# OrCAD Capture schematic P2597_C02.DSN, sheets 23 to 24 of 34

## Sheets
23 11_SDcard Slot: size Custom
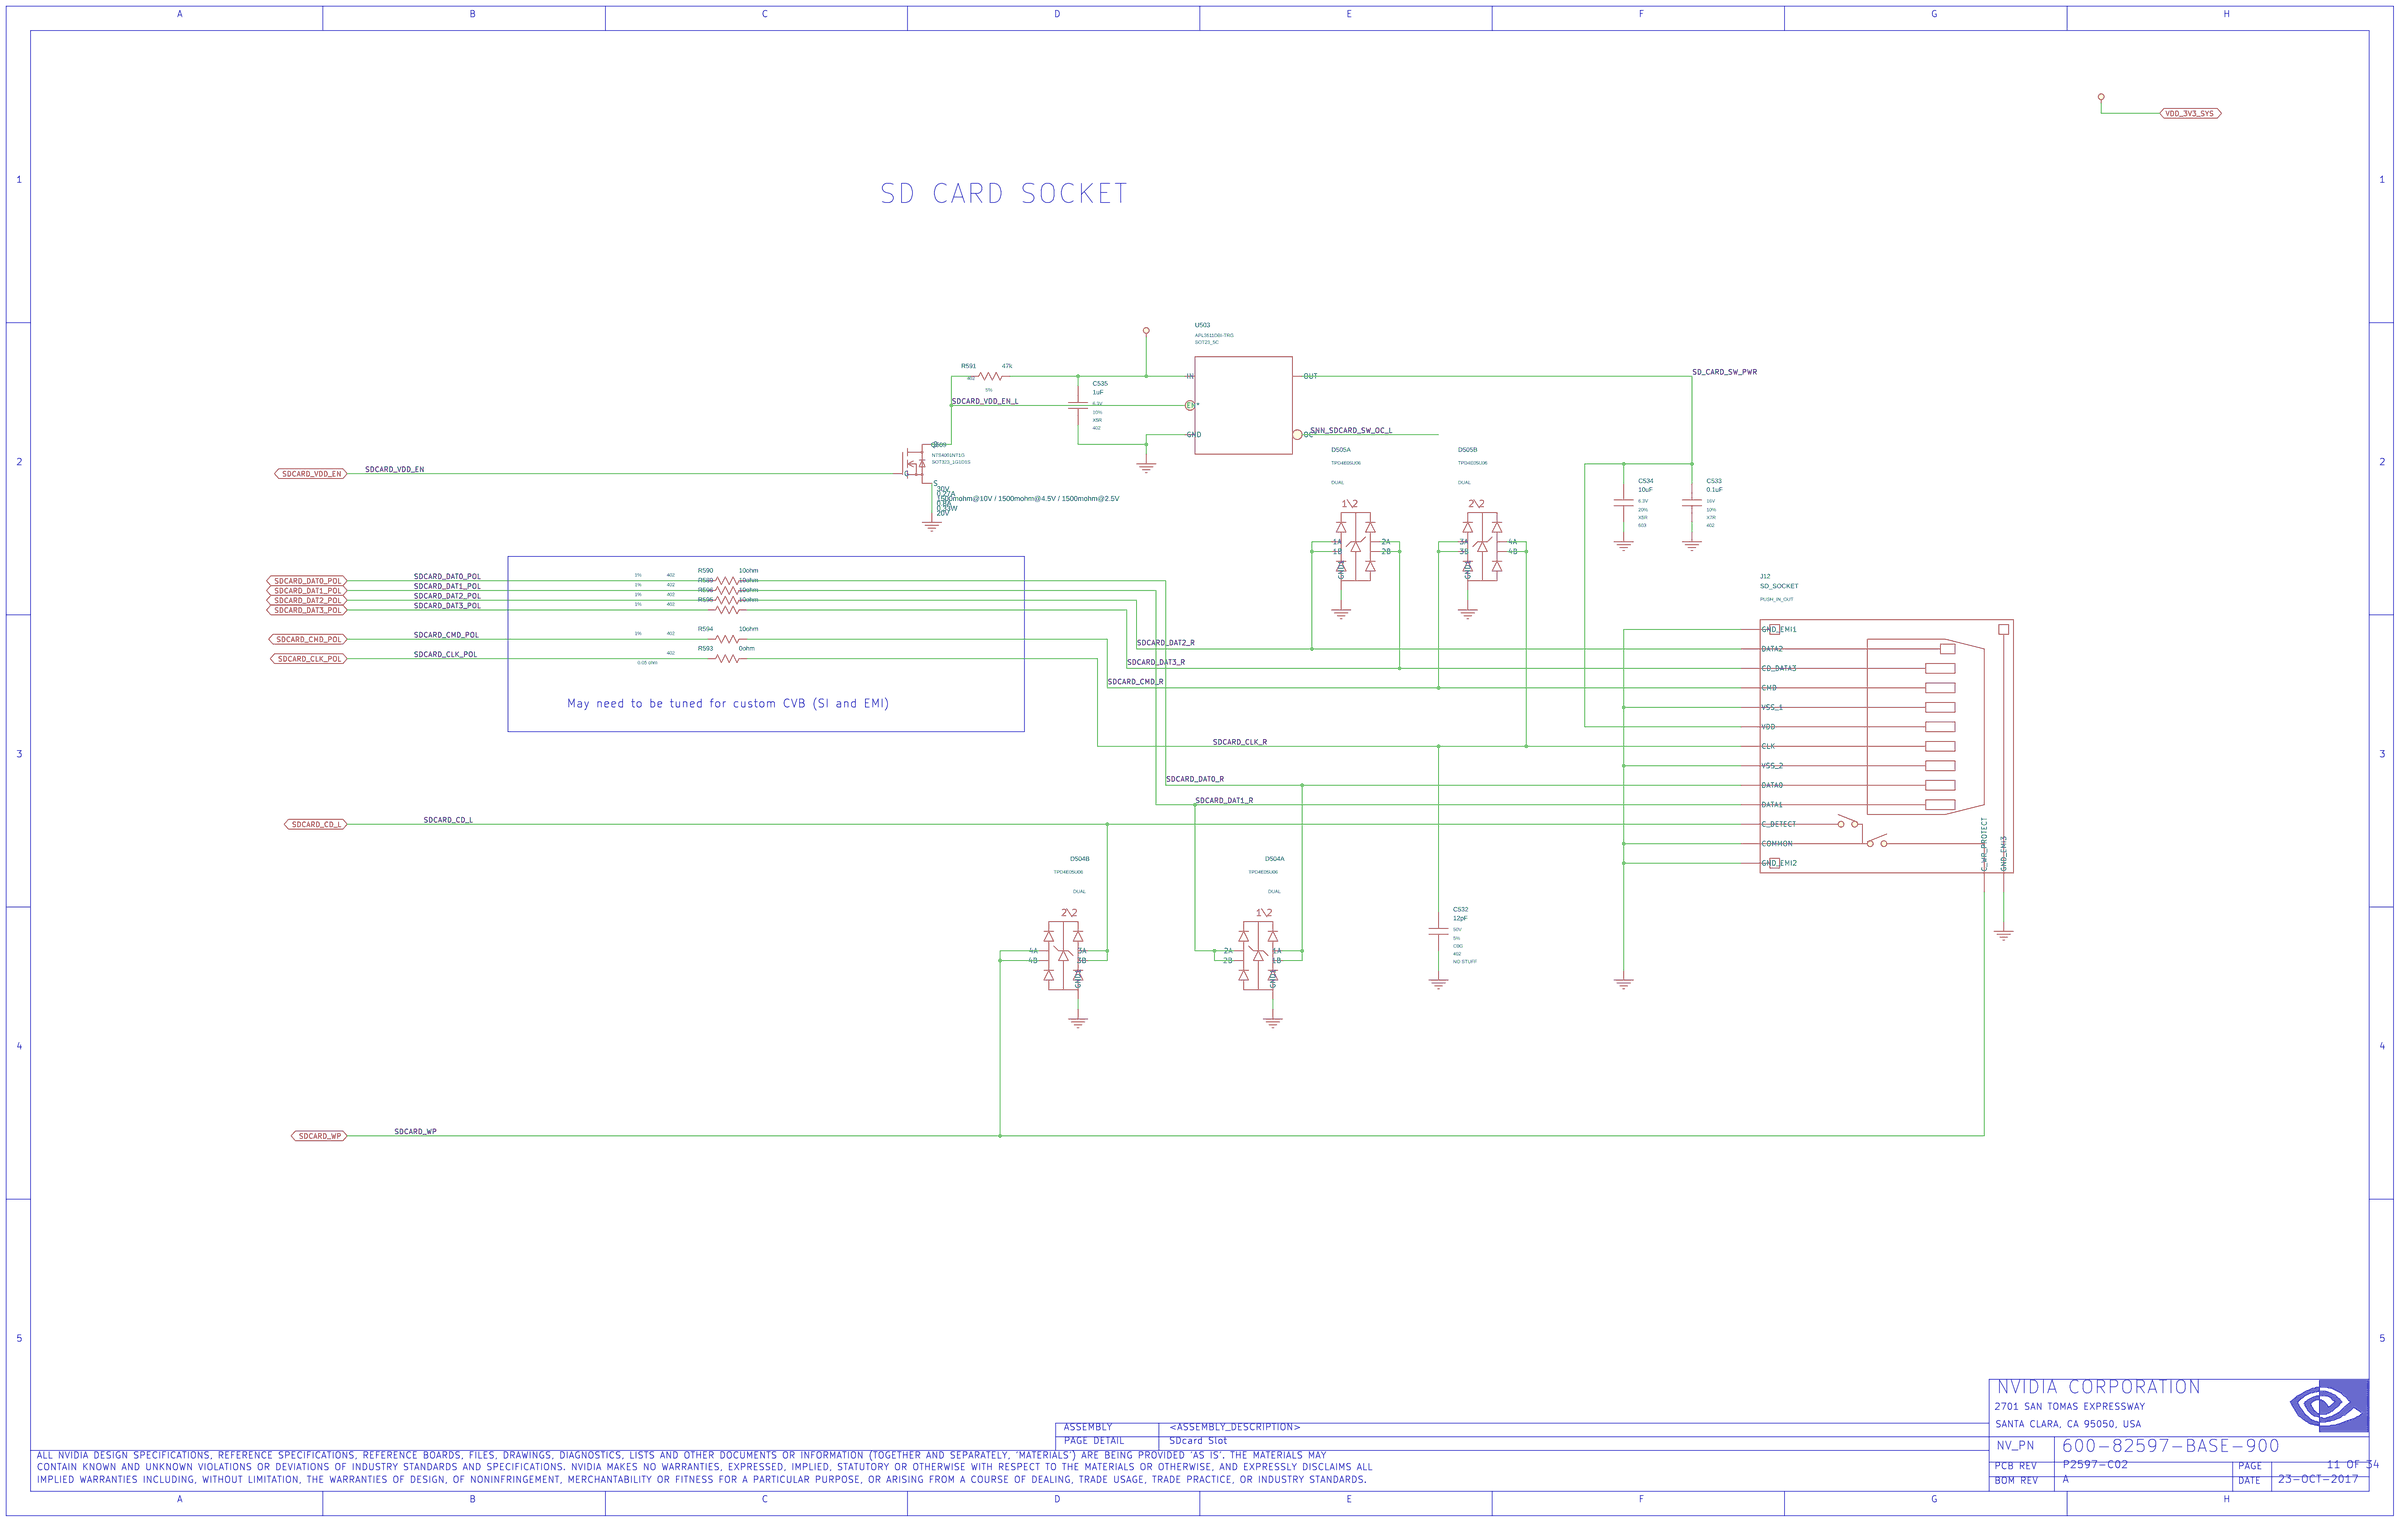
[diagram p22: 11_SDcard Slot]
24 10_M.2 KEY E: size Custom
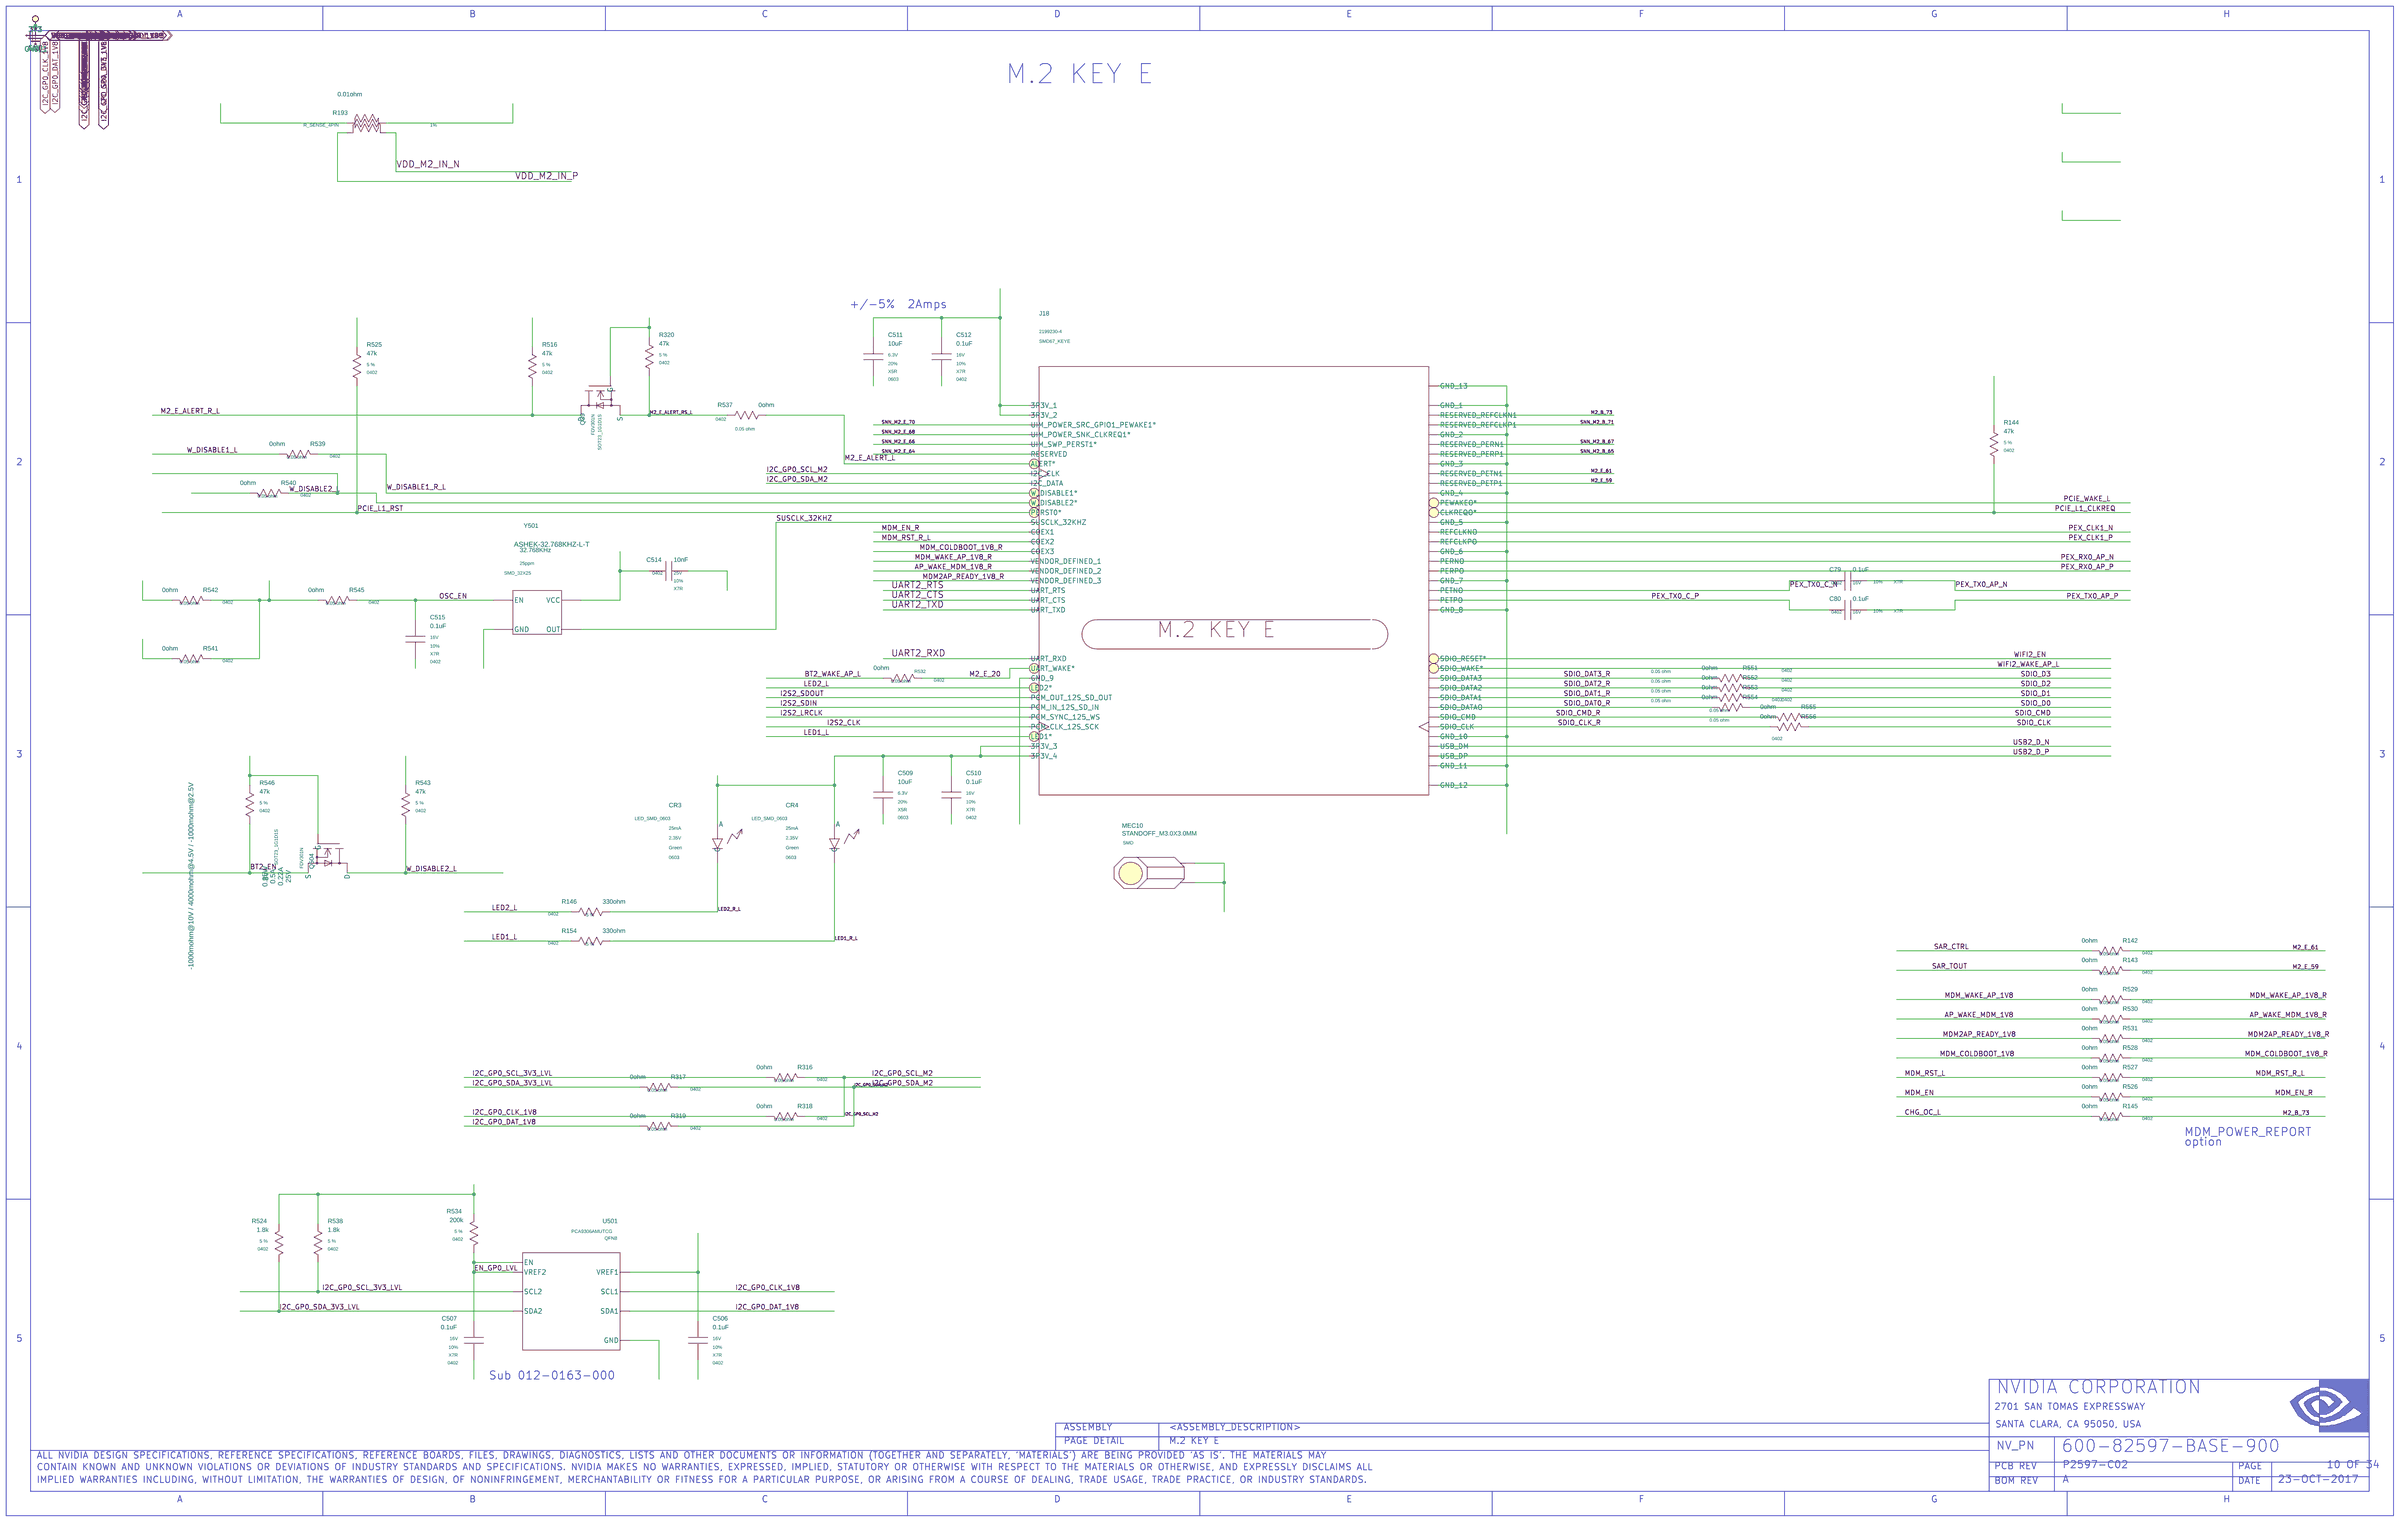
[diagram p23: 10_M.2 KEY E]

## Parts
sheet 10_M.2 KEY E
C79  0.1uF  [0402]
C80  0.1uF  [0402]
C506  0.1uF  [0402]
C507  0.1uF  [0402]
C509  10uF  [0603]
C510  0.1uF  [0402]
C511  10uF  [0603]
C512  0.1uF  [0402]
C514  10nF  [0402]
C515  0.1uF  [0402]
CR3  LED  [LED_SMD_0603_ST]
CR4  LED  [LED_SMD_0603_ST]
J18  CON_M2_PCI_EXP  [CON_MINIPEX_067_SMT_RA_M2_KEYE]
MEC10  MEC_STANDOFF2  [MEC_HOLE_PEM_NTH_430P]
Q39  Q_FET_N_ENH  [SOT23]
Q504  Q_FET_N_ENH  [SOT23]
R142  0ohm  [0402]
R143  0ohm  [0402]
R144  47k  [0402]
R145  0ohm  [0402]
R146  330ohm  [0402]
R154  330ohm  [0402]
R193  0.01ohm  [RES_04_SMD_015X032]
R316  0ohm  [0402]
R317  0ohm  [0402]
R318  0ohm  [0402]
R319  0ohm  [0402]
R320  47k  [0402]
R516  47k  [0402]
R524  1.8k  [0402]
R525  47k  [0402]
R526  0ohm  [0402]
R527  0ohm  [0402]
R528  0ohm  [0402]
R529  0ohm  [0402]
R530  0ohm  [0402]
R531  0ohm  [0402]
R532  0ohm  [0402]
R534  200k  [0402]
R537  0ohm  [0402]
R538  1.8k  [0402]
R539  0ohm  [0402]
R540  0ohm  [0402]
R541  0ohm  [0402]
R542  0ohm  [0402]
R543  47k  [0402]
R545  0ohm  [0402]
R546  47k  [0402]
R551  0ohm  [0402]
R552  0ohm  [0402]
R553  0ohm  [0402]
R554  0ohm  [0402]
R555  0ohm  [0402]
R556  0ohm  [0402]
U501  U_I2C_PCA9306  [QFN008Q_P050_0016X0016]
Y501  32.768KHz  [XTAL_SMD_4_032X025]
sheet 11_SDcard Slot
C532  12pF  [402]
C533  0.1uF  [402]
C534  10uF  [603]
C535  1uF  [402]
D504  D_ESD_DIFFPAIR#1  [TSLP10_P050_025X010]  (sections A,B)
D505  D_ESD_DIFFPAIR#1  [TSLP10_P050_025X010]  (sections A,B)
J12  CON_SD_SOCKET  [CON_SD_012_SMD_RA]
Q509  Q_FET_N_ENH  [SOT323]
R589  10ohm  [402]
R590  10ohm  [402]
R591  47k  [402]
R593  0ohm  [402]
R594  10ohm  [402]
R595  10ohm  [402]
R596  10ohm  [402]
U503  U_POWER_SW  [SOT23_5]

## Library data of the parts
C79 = C#1: ASSEMBLY: PEX_MINI; CDS_LIB: discrete; CDS_PART_NAME: C_0402-0.1UF,X7R,10%,16V,036-0014-000; CDS_PHYS_PART_NAME: C_0402-0.1UF,X7R,10%,16V,036-0014-000-0.1UF,036-0014-000; CDS_SEC: 1; CHIPS_PART_NAME: C; DEVICE_TYPENAME: C_0402-01UFX7R1016V036-0014-000-01UF036-0014-000; DRAWING: @P2597_C02_LIB.P2597_C02(SCH_1):PAGE10; MAT: X7R; MAX_VOLTAGE: 16V; NV_PN: 036-0014-000; PATH: I307; PHYS_PAGE: 10; ROT: 0; SEC: 1; SIGNAL_MODEL: nv_cap; TOL: 10%; VER: 2; XY: (-3000,6150)
C80 = C#1: ASSEMBLY: PEX_MINI; CDS_LIB: discrete; CDS_PART_NAME: C_0402-0.1UF,X7R,10%,16V,036-0014-000; CDS_PHYS_PART_NAME: C_0402-0.1UF,X7R,10%,16V,036-0014-000-0.1UF,036-0014-000; CDS_SEC: 1; CHIPS_PART_NAME: C; DEVICE_TYPENAME: C_0402-01UFX7R1016V036-0014-000-01UF036-0014-000; DRAWING: @P2597_C02_LIB.P2597_C02(SCH_1):PAGE10; MAT: X7R; MAX_VOLTAGE: 16V; NV_PN: 036-0014-000; PATH: I308; PHYS_PAGE: 10; ROT: 0; SEC: 1; SIGNAL_MODEL: nv_cap; TOL: 10%; VER: 2; XY: (-3000,6000)
C506 = C: ASSEMBLY: GEN1_CONV; CDS_LIB: discrete; CDS_PART_NAME: C_0402-0.1UF,X7R,10%,16V,036-0014-000; CDS_PHYS_PART_NAME: C_0402-0.1UF,X7R,10%,16V,036-0014-000-0.1UF,036-0014-000; CDS_SEC: 1; DEVICE_TYPENAME: C_0402-01UFX7R1016V036-0014-000-01UF036-0014-000; DRAWING: @P2597_C02_LIB.P2597_C02(SCH_1):PAGE10; MAT: X7R; MAX_VOLTAGE: 16V; NV_PN: 036-0014-000; PATH: I273; PHYS_PAGE: 10; ROT: 0; SEC: 1; SIGNAL_MODEL: nv_cap; TOL: 10%; VER: 1; XY: (-8900,2250)
C507 = C: ASSEMBLY: GEN1_CONV; CDS_LIB: discrete; CDS_PART_NAME: C_0402-0.1UF,X7R,10%,16V,036-0014-000; CDS_PHYS_PART_NAME: C_0402-0.1UF,X7R,10%,16V,036-0014-000-0.1UF,036-0014-000; CDS_SEC: 1; DEVICE_TYPENAME: C_0402-01UFX7R1016V036-0014-000-01UF036-0014-000; DRAWING: @P2597_C02_LIB.P2597_C02(SCH_1):PAGE10; MAT: X7R; MAX_VOLTAGE: 16V; NV_PN: 036-0014-000; PATH: I267; PHYS_PAGE: 10; ROT: 2; SEC: 1; SIGNAL_MODEL: nv_cap; TOL: 10%; VER: 1; XY: (-10050,2250)
C509 = C: ASSEMBLY: PEX_MINI; CDS_LIB: discrete; CDS_PART_NAME: C_0603-10UF,X5R,20%,6.3V,039-0135-000; CDS_PHYS_PART_NAME: C_0603-10UF,X5R,20%,6.3V,039-0135-000-039-0135-000,10UF; CDS_SEC: 1; DEVICE_TYPENAME: C_0603-10UFX5R2063V039-0135-000-039-0135-00010UF; DRAWING: @P2597_C02_LIB.P2597_C02(SCH_1):PAGE10; MAT: X5R; MAX_VOLTAGE: 6.3V; NV_PN: 039-0135-000; PATH: I169; PHYS_PAGE: 10; ROT: 0; SEC: 1; SIGNAL_MODEL: DEFAULT_CAPACITOR_1e+07pF_2_1; TOL: 20%; VER: 1; XY: (-7950,5050)
C510 = C: ASSEMBLY: PEX_MINI; CDS_LIB: discrete; CDS_PART_NAME: C_0402-0.1UF,X7R,10%,16V,036-0014-000; CDS_PHYS_PART_NAME: C_0402-0.1UF,X7R,10%,16V,036-0014-000-0.1UF,036-0014-000; CDS_SEC: 1; DEVICE_TYPENAME: C_0402-01UFX7R1016V036-0014-000-01UF036-0014-000; DRAWING: @P2597_C02_LIB.P2597_C02(SCH_1):PAGE10; MAT: X7R; MAX_VOLTAGE: 16V; NV_PN: 036-0014-000; PATH: I171; PHYS_PAGE: 10; ROT: 0; SEC: 1; SIGNAL_MODEL: DEFAULT_CAPACITOR_100000pF_2_1; TOL: 10%; VER: 1; XY: (-7600,5050)
C511 = C: ASSEMBLY: PEX_MINI; CDS_LIB: discrete; CDS_PART_NAME: C_0603-10UF,X5R,20%,6.3V,039-0135-000; CDS_PHYS_PART_NAME: C_0603-10UF,X5R,20%,6.3V,039-0135-000-039-0135-000,10UF; CDS_SEC: 1; DEVICE_TYPENAME: C_0603-10UFX5R2063V039-0135-000-039-0135-00010UF; DRAWING: @P2597_C02_LIB.P2597_C02(SCH_1):PAGE10; MAT: X5R; MAX_VOLTAGE: 6.3V; NV_PN: 039-0135-000; PATH: I165; PHYS_PAGE: 10; ROT: 0; SEC: 1; SIGNAL_MODEL: DEFAULT_CAPACITOR_1e+07pF_2_1; TOL: 20%; VER: 1; XY: (-8000,7300)
C512 = C: ASSEMBLY: PEX_MINI; CDS_LIB: discrete; CDS_PART_NAME: C_0402-0.1UF,X7R,10%,16V,036-0014-000; CDS_PHYS_PART_NAME: C_0402-0.1UF,X7R,10%,16V,036-0014-000-0.1UF,036-0014-000; CDS_SEC: 1; DEVICE_TYPENAME: C_0402-01UFX7R1016V036-0014-000-01UF036-0014-000; DRAWING: @P2597_C02_LIB.P2597_C02(SCH_1):PAGE10; MAT: X7R; MAX_VOLTAGE: 16V; NV_PN: 036-0014-000; PATH: I167; PHYS_PAGE: 10; ROT: 0; SEC: 1; SIGNAL_MODEL: DEFAULT_CAPACITOR_100000pF_2_1; TOL: 10%; VER: 1; XY: (-7650,7300)
C514 = C#1: ASSEMBLY: PEX_MINI; CDS_LIB: discrete; CDS_PART_NAME: C_0402-10NF,X7R,10%,25V,036-0019-000; CDS_PHYS_PART_NAME: C_0402-10NF,X7R,10%,25V,036-0019-000-036-0019-000,10NF; CDS_SEC: 1; CHIPS_PART_NAME: C; DEVICE_TYPENAME: C_0402-10NFX7R1025V036-0019-000-036-0019-00010NF; DRAWING: @P2597_C02_LIB.P2597_C02(SCH_1):PAGE10; MAT: X7R; MAX_VOLTAGE: 25V; NV_PN: 036-0019-000; PATH: I285; PHYS_PAGE: 10; ROT: 0; SEC: 1; SIGNAL_MODEL: nv_cap; TOL: 10%; VER: 2; XY: (-9050,6200)
C515 = C: ASSEMBLY: PEX_MINI; CDS_LIB: discrete; CDS_PART_NAME: C_0402-0.1UF,X7R,10%,16V,036-0014-000; CDS_PHYS_PART_NAME: C_0402-0.1UF,X7R,10%,16V,036-0014-000-0.1UF,036-0014-000; CDS_SEC: 1; DEVICE_TYPENAME: C_0402-01UFX7R1016V036-0014-000-01UF036-0014-000; DRAWING: @P2597_C02_LIB.P2597_C02(SCH_1):PAGE10; MAT: X7R; MAX_VOLTAGE: 16V; NV_PN: 036-0014-000; PATH: I139; PHYS_PAGE: 10; ROT: 0; SEC: 1; SIGNAL_MODEL: DEFAULT_CAPACITOR_100000pF_2_1; TOL: 10%; VER: 1; XY: (-10350,5850)
CR3 = LED: ASSEMBLY: PEX_MINI; CDS_LIB: discrete; CDS_PART_NAME: LED_0603-LED_SMD_0603,5V,60MA,2.35V,25MA,GREEN,092-0073-000; CDS_PHYS_PART_NAME: LED_0603-LED_SMD_0603,5V,60MA,2.35V,25MA,GREEN,092-0073-000-092-0073-000; CDS_SEC: 1; CONTINUOUS_CURRENT: 25mA; DEVICE_TYPENAME: LED_0603-LED_SMD_06035V60MA235V25MAGREEN092-0073-000-092-0073-000; DRAWING: @P2597_C02_LIB.P2597_C02(SCH_1):PAGE10; FORWARD_VOLTAGE: 2.35V; MAX_CURRENT: 60mA; MAX_VOLTAGE: 5V; NV_COLOR: Green; NV_NAME: LED_SMD_0603; NV_PN: 092-0073-000; PACK_TYPE: 0603; PATH: I107; PHYS_PAGE: 10; ROT: 0; SEC: 1; SEC_TYPE: 0603; VER: 1; XY: (-8800,4800)
CR4 = LED: ASSEMBLY: PEX_MINI; CDS_LIB: discrete; CDS_PART_NAME: LED_0603-LED_SMD_0603,5V,60MA,2.35V,25MA,GREEN,092-0073-000; CDS_PHYS_PART_NAME: LED_0603-LED_SMD_0603,5V,60MA,2.35V,25MA,GREEN,092-0073-000-092-0073-000; CDS_SEC: 1; CONTINUOUS_CURRENT: 25mA; DEVICE_TYPENAME: LED_0603-LED_SMD_06035V60MA235V25MAGREEN092-0073-000-092-0073-000; DRAWING: @P2597_C02_LIB.P2597_C02(SCH_1):PAGE10; FORWARD_VOLTAGE: 2.35V; MAX_CURRENT: 60mA; MAX_VOLTAGE: 5V; NV_COLOR: Green; NV_NAME: LED_SMD_0603; NV_PN: 092-0073-000; PACK_TYPE: 0603; PATH: I106; PHYS_PAGE: 10; ROT: 0; SEC: 1; SEC_TYPE: 0603; VER: 1; XY: (-8200,4800)
J18 = CON_M2_PCI_EXP: ANGLE: 90; ASSEMBLY: PEX_MINI; CDS_LIB: electro_mechanic; CDS_PART_NAME: CON_M2_PCI_EXP_SMD67_KEYE-2199230-4,FEMALE,0.5MM,90,N/A,NO,NO,NO,NO,50.0 V,0.5 A,080-1243-000; CDS_PHYS_PART_NAME: CON_M2_PCI_EXP_SMD67_KEYE-2199230-4,FEMALE,0.5MM,90,N/A,NO,NO,NO,NO,50.0 V,0.5 A,080-1243-000-080-1243-000; CDS_SEC: 1; DEVICE_TYPENAME: CON_M2_PCI_EXP_SMD67_KEYE-2199230-4FEMALE05MM90NANONONONO500V05A080-1243-000-080-1243-000; DRAWING: @P2597_C02_LIB.P2597_C02(SCH_1):PAGE10; EMI_GROUND_TAB: NO; GENDER: FEMALE; LATCHING: NO; MAX_CURRENT: 0.5 A; MAX_VOLTAGE: 50.0 V; NV_NAME: 2199230-4; NV_PN: 080-1243-000; PACK_TYPE: SMD67_KEYE; PATH: I343; PHYS_PAGE: 10; PITCH: 0.5mm; REFLOW: N/A; ROT: 0; SEC: 1; SHIELDED: NO; SHROUDED: NO; VER: 2; XY: (-6150,6150)
MEC10 = MEC_STANDOFF2: ASSEMBLY: PEX_MINI; CDS_LIB: mechanic; CDS_PART_NAME: MEC_STANDOFF2_SMD-STANDOFF_M3.0X3.0MM,320-0965-000; CDS_PHYS_PART_NAME: MEC_STANDOFF2_SMD-STANDOFF_M3.0X3.0MM,320-0965-000-320-0965-000; CDS_SEC: 1; DEVICE_TYPENAME: MEC_STANDOFF2_SMD-STANDOFF_M30X30MM320-0965-000-320-0965-000; DRAWING: @P2597_C02_LIB.P2597_C02(SCH_1):PAGE10; NV_NAME: STANDOFF_M3.0X3.0MM; NV_PN: 320-0965-000; PACK_TYPE: SMD; PATH: I260; PHYS_PAGE: 10; ROT: 0; SEC: 1; SEC_TYPE: SMD; VER: 1; XY: (-6550,4650)
Q39 = Q_FET_N_ENH#2: ASSEMBLY: PEX_MINI; CDS_LIB: discrete; CDS_PART_NAME: Q_FET_N_ENH_SOT23_1G1D1S-FDV301N,25V,-1000MOHM@10V / 4000MOHM@4.5V / -1000MOHM@2.5V,0.22A,0.5A,8V,0.35W,[ ]@10V / [ ]@4.5V / [A; CDS_PHYS_PART_NAME: Q_FET_N_ENH_SOT23_1G1D1S-FDV301N,25V,-1000MOHM@10V / 4000MOHM@4.5V / -1000MOHM@2.5V,0.22A,0.5A,8V,0.35W,[ ]@10V / [ ]@4.5V / [B; CDS_SEC: 1; CONTINUOUS_CURRENT: 0.22A; CaptureCellPackProp: Q_FET_N_ENH__sym_2##2; DEVICE_TYPENAME: Q_FET_N_ENH_SOT23_1G1D1S-FDV301N25V-1000MOHM10V4000MOHM45V-1000MOHM25V022A05A8V035W10V45VB; DRAWING: @P2597_C02_LIB.P2597_C02(SCH_1):PAGE10; MAX_CURRENT: 0.5A; MAX_VOLTAGE: 25V; MAX_WATTAGE: 0.35W; NV_NAME: FDV301N; NV_PN: 300-0494-000; PACK_TYPE: SOT23_1G1D1S; PATH: I338; PHYS_PAGE: 10; Q_G: [ ]@10V / [ ]@4.5V / [ ]@2.5V; ROT: 3; R_DS_ON: -1000mohm@10V / 4000mohm@4.5V / -1000mohm@2.5V; SEC: 1; SEC_TYPE: SOT23_1G1D1S; VER: 2; V_BE_GS: 8V; XY: (-9400,7100)
Q504 = Q_FET_N_ENH#2: ASSEMBLY: PEX_MINI; CDS_LIB: discrete; CDS_PART_NAME: Q_FET_N_ENH_SOT23_1G1D1S-FDV301N,25V,-1000MOHM@10V / 4000MOHM@4.5V / -1000MOHM@2.5V,0.22A,0.5A,8V,0.35W,[ ]@10V / [ ]@4.5V / [A; CDS_PHYS_PART_NAME: Q_FET_N_ENH_SOT23_1G1D1S-FDV301N,25V,-1000MOHM@10V / 4000MOHM@4.5V / -1000MOHM@2.5V,0.22A,0.5A,8V,0.35W,[ ]@10V / [ ]@4.5V / [B; CDS_SEC: 1; CONTINUOUS_CURRENT: 0.22A; CaptureCellPackProp: Q_FET_N_ENH__sym_2##2; DEVICE_TYPENAME: Q_FET_N_ENH_SOT23_1G1D1S-FDV301N25V-1000MOHM10V4000MOHM45V-1000MOHM25V022A05A8V035W10V45VB; DRAWING: @P2597_C02_LIB.P2597_C02(SCH_1):PAGE10; MAX_CURRENT: 0.5A; MAX_VOLTAGE: 25V; MAX_WATTAGE: 0.35W; NV_NAME: FDV301N; NV_PN: 300-0494-000; PACK_TYPE: SOT23_1G1D1S; PATH: I181; PHYS_PAGE: 10; Q_G: [ ]@10V / [ ]@4.5V / [ ]@2.5V; ROT: 5; R_DS_ON: -1000mohm@10V / 4000mohm@4.5V / -1000mohm@2.5V; SEC: 1; SEC_TYPE: SOT23_1G1D1S; VER: 2; V_BE_GS: 8V; XY: (-10800,4750)
R142 = R: ASSEMBLY: PEX_MINI; CDS_LIB: discrete; CDS_PART_NAME: R_0402-0OHM,0.05 OHM,62.5MW,195-2655-000; CDS_PHYS_PART_NAME: R_0402-0OHM,0.05 OHM,62.5MW,195-2655-000-0OHM,195-2655-000; CDS_SEC: 1; DEVICE_TYPENAME: R_0402-0OHM005OHM625MW195-2655-000-0OHM195-2655-000; DRAWING: @P2597_C02_LIB.P2597_C02(SCH_1):PAGE10; MAX_WATTAGE: 62.5mW; NV_PN: 195-2655-000; PATH: I255; PHYS_PAGE: 10; ROT: 2; SEC: 1; SIGNAL_MODEL: nv_res; TOL: 0.05 ohm; VER: 1; XY: (-1650,4250)
R143 = R: ASSEMBLY: PEX_MINI; CDS_LIB: discrete; CDS_PART_NAME: R_0402-0OHM,0.05 OHM,62.5MW,195-2655-000; CDS_PHYS_PART_NAME: R_0402-0OHM,0.05 OHM,62.5MW,195-2655-000-0OHM,195-2655-000; CDS_SEC: 1; DEVICE_TYPENAME: R_0402-0OHM005OHM625MW195-2655-000-0OHM195-2655-000; DRAWING: @P2597_C02_LIB.P2597_C02(SCH_1):PAGE10; MAX_WATTAGE: 62.5mW; NV_PN: 195-2655-000; PATH: I254; PHYS_PAGE: 10; ROT: 2; SEC: 1; SIGNAL_MODEL: nv_res; TOL: 0.05 ohm; VER: 1; XY: (-1650,4150)
R144 = R#1: ASSEMBLY: PEX_MINI; CDS_LIB: discrete; CDS_PART_NAME: R_0402-47K,5 %,62.5MW,195-0599-000; CDS_PHYS_PART_NAME: R_0402-47K,5 %,62.5MW,195-0599-000-195-0599-000,47K; CDS_SEC: 1; CHIPS_PART_NAME: R; DEVICE_TYPENAME: R_0402-47K5625MW195-0599-000-195-0599-00047K; DRAWING: @P2597_C02_LIB.P2597_C02(SCH_1):PAGE10; MAX_WATTAGE: 62.5mW; NV_PN: 195-0599-000; PATH: I95; PHYS_PAGE: 10; ROT: 0; SEC: 1; SIGNAL_MODEL: nv_res; TOL: 5 %; VER: 2; XY: (-2250,6850)
R145 = R: ASSEMBLY: PEX_MINI; CDS_LIB: discrete; CDS_PART_NAME: R_0402-0OHM,0.05 OHM,62.5MW,195-2655-000; CDS_PHYS_PART_NAME: R_0402-0OHM,0.05 OHM,62.5MW,195-2655-000-0OHM,195-2655-000; CDS_SEC: 1; DEVICE_TYPENAME: R_0402-0OHM005OHM625MW195-2655-000-0OHM195-2655-000; DRAWING: @P2597_C02_LIB.P2597_C02(SCH_1):PAGE10; MAX_WATTAGE: 62.5mW; NV_PN: 195-2655-000; PATH: I304; PHYS_PAGE: 10; ROT: 2; SEC: 1; SIGNAL_MODEL: nv_res; TOL: 0.05 ohm; VER: 1; XY: (-1650,3400)
R146 = R: ASSEMBLY: PEX_MINI; CDS_LIB: discrete; CDS_PART_NAME: R_0402-330OHM,5 %,62.5MW,195-0569-000; CDS_PHYS_PART_NAME: R_0402-330OHM,5 %,62.5MW,195-0569-000-195-0569-000,330OHM; CDS_SEC: 1; DEVICE_TYPENAME: R_0402-330OHM5625MW195-0569-000-195-0569-000330OHM; DRAWING: @P2597_C02_LIB.P2597_C02(SCH_1):PAGE10; MAX_WATTAGE: 62.5mW; NV_PN: 195-0569-000; PATH: I129; PHYS_PAGE: 10; ROT: 0; SEC: 1; SIGNAL_MODEL: nv_res; TOL: 5 %; VER: 1; XY: (-9450,4450)
R154 = R: ASSEMBLY: PEX_MINI; CDS_LIB: discrete; CDS_PART_NAME: R_0402-330OHM,5 %,62.5MW,195-0569-000; CDS_PHYS_PART_NAME: R_0402-330OHM,5 %,62.5MW,195-0569-000-195-0569-000,330OHM; CDS_SEC: 1; DEVICE_TYPENAME: R_0402-330OHM5625MW195-0569-000-195-0569-000330OHM; DRAWING: @P2597_C02_LIB.P2597_C02(SCH_1):PAGE10; MAX_WATTAGE: 62.5mW; NV_PN: 195-0569-000; PATH: I130; PHYS_PAGE: 10; ROT: 0; SEC: 1; SIGNAL_MODEL: nv_res; TOL: 5 %; VER: 1; XY: (-9450,4300)
R193 = R_SENSE_4PIN: ASSEMBLY: CONN_POWER; CDS_LIB: discrete; CDS_PART_NAME: R_SENSE_4PIN_R_SENSE_4PIN-0.01OHM,1%,1W,[ ],215-0142-000; CDS_PHYS_PART_NAME: R_SENSE_4PIN_R_SENSE_4PIN-0.01OHM,1%,1W,[ ],215-0142-000-0.01OHM,215-0142-000; CDS_SEC: 1; DEVICE_TYPENAME: R_SENSE_4PIN_R_SENSE_4PIN-001OHM11W215-0142-000-001OHM215-0142-000; DRAWING: @P2597_C02_LIB.P2597_C02(SCH_1):PAGE10; MAX_WATTAGE: 1W; NV_PN: 215-0142-000; PATH: I298; PHYS_PAGE: 10; ROT: 0; SEC: 1; SIGNAL_MODEL: nv_res_sense_4p_noxnet; TEMP_COEF: [ ]; TOL: 1%; VER: 1; XY: (-10600,8500)
R316 = R: ASSEMBLY: PEX_MINI; CDS_LIB: discrete; CDS_PART_NAME: R_0402-0OHM,0.05 OHM,62.5MW,195-2655-000; CDS_PHYS_PART_NAME: R_0402-0OHM,0.05 OHM,62.5MW,195-2655-000-0OHM,195-2655-000; CDS_SEC: 1; DEVICE_TYPENAME: R_0402-0OHM005OHM625MW195-2655-000-0OHM195-2655-000; DRAWING: @P2597_C02_LIB.P2597_C02(SCH_1):PAGE10; MAX_WATTAGE: 62.5mW; NV_PN: 195-2655-000; PATH: I322; PHYS_PAGE: 10; ROT: 2; SEC: 1; SIGNAL_MODEL: nv_res; TOL: 0.05 ohm; VER: 1; XY: (-8450,3600)
R317 = R: ASSEMBLY: PEX_MINI; CDS_LIB: discrete; CDS_PART_NAME: R_0402-0OHM,0.05 OHM,62.5MW,195-2655-000; CDS_PHYS_PART_NAME: R_0402-0OHM,0.05 OHM,62.5MW,195-2655-000-0OHM,195-2655-000; CDS_SEC: 1; DEVICE_TYPENAME: R_0402-0OHM005OHM625MW195-2655-000-0OHM195-2655-000; DRAWING: @P2597_C02_LIB.P2597_C02(SCH_1):PAGE10; MAX_WATTAGE: 62.5mW; NV_PN: 195-2655-000; PATH: I323; PHYS_PAGE: 10; ROT: 2; SEC: 1; SIGNAL_MODEL: nv_res; TOL: 0.05 ohm; VER: 1; XY: (-9100,3550)
R318 = R: ASSEMBLY: PEX_MINI; CDS_LIB: discrete; CDS_PART_NAME: R_0402-0OHM,0.05 OHM,62.5MW,195-2655-000; CDS_PHYS_PART_NAME: R_0402-0OHM,0.05 OHM,62.5MW,195-2655-000-0OHM,195-2655-000; CDS_SEC: 1; DEVICE_TYPENAME: R_0402-0OHM005OHM625MW195-2655-000-0OHM195-2655-000; DRAWING: @P2597_C02_LIB.P2597_C02(SCH_1):PAGE10; MAX_WATTAGE: 62.5mW; NV_PN: 195-2655-000; PATH: I326; PHYS_PAGE: 10; ROT: 2; SEC: 1; SIGNAL_MODEL: nv_res; TOL: 0.05 ohm; VER: 1; XY: (-8450,3400)
R319 = R: ASSEMBLY: PEX_MINI; CDS_LIB: discrete; CDS_PART_NAME: R_0402-0OHM,0.05 OHM,62.5MW,195-2655-000; CDS_PHYS_PART_NAME: R_0402-0OHM,0.05 OHM,62.5MW,195-2655-000-0OHM,195-2655-000; CDS_SEC: 1; DEVICE_TYPENAME: R_0402-0OHM005OHM625MW195-2655-000-0OHM195-2655-000; DRAWING: @P2597_C02_LIB.P2597_C02(SCH_1):PAGE10; MAX_WATTAGE: 62.5mW; NV_PN: 195-2655-000; PATH: I327; PHYS_PAGE: 10; ROT: 2; SEC: 1; SIGNAL_MODEL: nv_res; TOL: 0.05 ohm; VER: 1; XY: (-9100,3350)
R320 = R#1: ASSEMBLY: PEX_MINI; CDS_LIB: discrete; CDS_PART_NAME: R_0402-47K,5 %,62.5MW,195-0599-000; CDS_PHYS_PART_NAME: R_0402-47K,5 %,62.5MW,195-0599-000-195-0599-000,47K; CDS_SEC: 1; CHIPS_PART_NAME: R; DEVICE_TYPENAME: R_0402-47K5625MW195-0599-000-195-0599-00047K; DRAWING: @P2597_C02_LIB.P2597_C02(SCH_1):PAGE10; MAX_WATTAGE: 62.5mW; NV_PN: 195-0599-000; PATH: I337; PHYS_PAGE: 10; ROT: 0; SEC: 1; SIGNAL_MODEL: nv_res; TOL: 5 %; VER: 2; XY: (-9150,7300)
R516 = R#1: ASSEMBLY: PM342; CDS_LIB: discrete; CDS_PART_NAME: R_0402-47K,5 %,62.5MW,195-0599-000; CDS_PHYS_PART_NAME: R_0402-47K,5 %,62.5MW,195-0599-000-195-0599-000,47K; CDS_SEC: 1; CHIPS_PART_NAME: R; DEVICE_TYPENAME: R_0402-47K5625MW195-0599-000-195-0599-00047K; DRAWING: @P2597_C02_LIB.P2597_C02(SCH_1):PAGE10; MAX_WATTAGE: 62.5mW; NV_PN: 195-0599-000; PATH: I313; PHYS_PAGE: 10; ROT: 0; SEC: 1; SIGNAL_MODEL: nv_res; TOL: 5 %; VER: 2; XY: (-9750,7250)
R524 = R#1: ASSEMBLY: GEN1_CONV; CDS_LIB: discrete; CDS_PART_NAME: R_0402-1.8K,5 %,62.5MW,195-0528-000; CDS_PHYS_PART_NAME: R_0402-1.8K,5 %,62.5MW,195-0528-000-1.8K,195-0528-000; CDS_SEC: 1; CHIPS_PART_NAME: R; DEVICE_TYPENAME: R_0402-18K5625MW195-0528-000-18K195-0528-000; DRAWING: @P2597_C02_LIB.P2597_C02(SCH_1):PAGE10; MAX_WATTAGE: 62.5mW; NV_PN: 195-0528-000; PATH: I264; PHYS_PAGE: 10; ROT: 2; SEC: 1; SIGNAL_MODEL: nv_res; TOL: 5 %; VER: 2; XY: (-11050,2750)
R525 = R#1: ASSEMBLY: PEX_MINI; CDS_LIB: discrete; CDS_PART_NAME: R_0402-47K,5 %,62.5MW,195-0599-000; CDS_PHYS_PART_NAME: R_0402-47K,5 %,62.5MW,195-0599-000-195-0599-000,47K; CDS_SEC: 1; CHIPS_PART_NAME: R; DEVICE_TYPENAME: R_0402-47K5625MW195-0599-000-195-0599-00047K; DRAWING: @P2597_C02_LIB.P2597_C02(SCH_1):PAGE10; MAX_WATTAGE: 62.5mW; NV_PN: 195-0599-000; PATH: I98; PHYS_PAGE: 10; ROT: 0; SEC: 1; SIGNAL_MODEL: nv_res; TOL: 5 %; VER: 2; XY: (-10650,7250)
R526 = R: ASSEMBLY: PEX_MINI; CDS_LIB: discrete; CDS_PART_NAME: R_0402-0OHM,0.05 OHM,62.5MW,195-2655-000; CDS_PHYS_PART_NAME: R_0402-0OHM,0.05 OHM,62.5MW,195-2655-000-0OHM,195-2655-000; CDS_SEC: 1; DEVICE_TYPENAME: R_0402-0OHM005OHM625MW195-2655-000-0OHM195-2655-000; DRAWING: @P2597_C02_LIB.P2597_C02(SCH_1):PAGE10; MAX_WATTAGE: 62.5mW; NV_PN: 195-2655-000; PATH: I207; PHYS_PAGE: 10; ROT: 2; SEC: 1; SIGNAL_MODEL: nv_res; TOL: 0.05 ohm; VER: 1; XY: (-1650,3500)
R527 = R: ASSEMBLY: PEX_MINI; CDS_LIB: discrete; CDS_PART_NAME: R_0402-0OHM,0.05 OHM,62.5MW,195-2655-000; CDS_PHYS_PART_NAME: R_0402-0OHM,0.05 OHM,62.5MW,195-2655-000-0OHM,195-2655-000; CDS_SEC: 1; DEVICE_TYPENAME: R_0402-0OHM005OHM625MW195-2655-000-0OHM195-2655-000; DRAWING: @P2597_C02_LIB.P2597_C02(SCH_1):PAGE10; MAX_WATTAGE: 62.5mW; NV_PN: 195-2655-000; PATH: I206; PHYS_PAGE: 10; ROT: 2; SEC: 1; SIGNAL_MODEL: nv_res; TOL: 0.05 ohm; VER: 1; XY: (-1650,3600)
R528 = R: ASSEMBLY: PEX_MINI; CDS_LIB: discrete; CDS_PART_NAME: R_0402-0OHM,0.05 OHM,62.5MW,195-2655-000; CDS_PHYS_PART_NAME: R_0402-0OHM,0.05 OHM,62.5MW,195-2655-000-0OHM,195-2655-000; CDS_SEC: 1; DEVICE_TYPENAME: R_0402-0OHM005OHM625MW195-2655-000-0OHM195-2655-000; DRAWING: @P2597_C02_LIB.P2597_C02(SCH_1):PAGE10; MAX_WATTAGE: 62.5mW; NV_PN: 195-2655-000; PATH: I204; PHYS_PAGE: 10; ROT: 2; SEC: 1; SIGNAL_MODEL: nv_res; TOL: 0.05 ohm; VER: 1; XY: (-1650,3700)
R529 = R: ASSEMBLY: PEX_MINI; CDS_LIB: discrete; CDS_PART_NAME: R_0402-0OHM,0.05 OHM,62.5MW,195-2655-000; CDS_PHYS_PART_NAME: R_0402-0OHM,0.05 OHM,62.5MW,195-2655-000-0OHM,195-2655-000; CDS_SEC: 1; DEVICE_TYPENAME: R_0402-0OHM005OHM625MW195-2655-000-0OHM195-2655-000; DRAWING: @P2597_C02_LIB.P2597_C02(SCH_1):PAGE10; MAX_WATTAGE: 62.5mW; NV_PN: 195-2655-000; PATH: I192; PHYS_PAGE: 10; ROT: 2; SEC: 1; SIGNAL_MODEL: nv_res; TOL: 0.05 ohm; VER: 1; XY: (-1650,4000)
R530 = R: ASSEMBLY: PEX_MINI; CDS_LIB: discrete; CDS_PART_NAME: R_0402-0OHM,0.05 OHM,62.5MW,195-2655-000; CDS_PHYS_PART_NAME: R_0402-0OHM,0.05 OHM,62.5MW,195-2655-000-0OHM,195-2655-000; CDS_SEC: 1; DEVICE_TYPENAME: R_0402-0OHM005OHM625MW195-2655-000-0OHM195-2655-000; DRAWING: @P2597_C02_LIB.P2597_C02(SCH_1):PAGE10; MAX_WATTAGE: 62.5mW; NV_PN: 195-2655-000; PATH: I200; PHYS_PAGE: 10; ROT: 2; SEC: 1; SIGNAL_MODEL: nv_res; TOL: 0.05 ohm; VER: 1; XY: (-1650,3900)
R531 = R: ASSEMBLY: PEX_MINI; CDS_LIB: discrete; CDS_PART_NAME: R_0402-0OHM,0.05 OHM,62.5MW,195-2655-000; CDS_PHYS_PART_NAME: R_0402-0OHM,0.05 OHM,62.5MW,195-2655-000-0OHM,195-2655-000; CDS_SEC: 1; DEVICE_TYPENAME: R_0402-0OHM005OHM625MW195-2655-000-0OHM195-2655-000; DRAWING: @P2597_C02_LIB.P2597_C02(SCH_1):PAGE10; MAX_WATTAGE: 62.5mW; NV_PN: 195-2655-000; PATH: I202; PHYS_PAGE: 10; ROT: 2; SEC: 1; SIGNAL_MODEL: nv_res; TOL: 0.05 ohm; VER: 1; XY: (-1650,3800)
R532 = R: ASSEMBLY: PEX_MINI; CDS_LIB: discrete; CDS_PART_NAME: R_0402-0OHM,0.05 OHM,62.5MW,195-2655-000; CDS_PHYS_PART_NAME: R_0402-0OHM,0.05 OHM,62.5MW,195-2655-000-0OHM,195-2655-000; CDS_SEC: 1; DEVICE_TYPENAME: R_0402-0OHM005OHM625MW195-2655-000-0OHM195-2655-000; DRAWING: @P2597_C02_LIB.P2597_C02(SCH_1):PAGE10; MAX_WATTAGE: 62.5mW; NV_PN: 195-2655-000; PATH: I173; PHYS_PAGE: 10; ROT: 2; SEC: 1; SIGNAL_MODEL: nv_res; TOL: 0.05 ohm; VER: 1; XY: (-7850,5650)
R534 = R#1: ASSEMBLY: GEN1_CONV; CDS_LIB: discrete; CDS_PART_NAME: R_0402-200K,5 %,62.5MW,195-0537-000; CDS_PHYS_PART_NAME: R_0402-200K,5 %,62.5MW,195-0537-000-195-0537-000,200K; CDS_SEC: 1; CHIPS_PART_NAME: R; DEVICE_TYPENAME: R_0402-200K5625MW195-0537-000-195-0537-000200K; DRAWING: @P2597_C02_LIB.P2597_C02(SCH_1):PAGE10; MAX_WATTAGE: 62.5mW; NV_PN: 195-0537-000; PATH: I269; PHYS_PAGE: 10; ROT: 2; SEC: 1; SIGNAL_MODEL: DEFAULT_RESISTOR_200000OHM_2_1; TOL: 5 %; VER: 2; XY: (-10050,2800)
R537 = R: ASSEMBLY: GPIO; CDS_LIB: discrete; CDS_PART_NAME: R_0402-0OHM,0.05 OHM,62.5MW,195-2655-000; CDS_PHYS_PART_NAME: R_0402-0OHM,0.05 OHM,62.5MW,195-2655-000-0OHM,195-2655-000; CDS_SEC: 1; DEVICE_TYPENAME: R_0402-0OHM005OHM625MW195-2655-000-0OHM195-2655-000; DRAWING: @P2597_C02_LIB.P2597_C02(SCH_1):PAGE10; MAX_WATTAGE: 62.5mW; NV_PN: 195-2655-000; PATH: I281; PHYS_PAGE: 10; ROT: 0; SEC: 1; SIGNAL_MODEL: nv_res; TOL: 0.05 ohm; VER: 1; XY: (-8650,7000)
R538 = R#1: ASSEMBLY: GEN1_CONV; CDS_LIB: discrete; CDS_PART_NAME: R_0402-1.8K,5 %,62.5MW,195-0528-000; CDS_PHYS_PART_NAME: R_0402-1.8K,5 %,62.5MW,195-0528-000-1.8K,195-0528-000; CDS_SEC: 1; CHIPS_PART_NAME: R; DEVICE_TYPENAME: R_0402-18K5625MW195-0528-000-18K195-0528-000; DRAWING: @P2597_C02_LIB.P2597_C02(SCH_1):PAGE10; MAX_WATTAGE: 62.5mW; NV_PN: 195-0528-000; PATH: I265; PHYS_PAGE: 10; ROT: 0; SEC: 1; SIGNAL_MODEL: nv_res; TOL: 5 %; VER: 2; XY: (-10850,2750)
R539 = R: ASSEMBLY: PEX_MINI; CDS_LIB: discrete; CDS_PART_NAME: R_0402-0OHM,0.05 OHM,62.5MW,195-2655-000; CDS_PHYS_PART_NAME: R_0402-0OHM,0.05 OHM,62.5MW,195-2655-000-0OHM,195-2655-000; CDS_SEC: 1; DEVICE_TYPENAME: R_0402-0OHM005OHM625MW195-2655-000-0OHM195-2655-000; DRAWING: @P2597_C02_LIB.P2597_C02(SCH_1):PAGE10; MAX_WATTAGE: 62.5mW; NV_PN: 195-2655-000; PATH: I258; PHYS_PAGE: 10; ROT: 2; SEC: 1; SIGNAL_MODEL: nv_res; TOL: 0.05 ohm; VER: 1; XY: (-10950,6800)
R540 = R: ASSEMBLY: PEX_MINI; CDS_LIB: discrete; CDS_PART_NAME: R_0402-0OHM,0.05 OHM,62.5MW,195-2655-000; CDS_PHYS_PART_NAME: R_0402-0OHM,0.05 OHM,62.5MW,195-2655-000-0OHM,195-2655-000; CDS_SEC: 1; DEVICE_TYPENAME: R_0402-0OHM005OHM625MW195-2655-000-0OHM195-2655-000; DRAWING: @P2597_C02_LIB.P2597_C02(SCH_1):PAGE10; MAX_WATTAGE: 62.5mW; NV_PN: 195-2655-000; PATH: I128; PHYS_PAGE: 10; ROT: 2; SEC: 1; SIGNAL_MODEL: nv_res; TOL: 0.05 ohm; VER: 1; XY: (-11100,6600)
R541 = R: ASSEMBLY: PEX_MINI; CDS_LIB: discrete; CDS_PART_NAME: R_0402-0OHM,0.05 OHM,62.5MW,195-2655-000; CDS_PHYS_PART_NAME: R_0402-0OHM,0.05 OHM,62.5MW,195-2655-000-0OHM,195-2655-000; CDS_SEC: 1; DEVICE_TYPENAME: R_0402-0OHM005OHM625MW195-2655-000-0OHM195-2655-000; DRAWING: @P2597_C02_LIB.P2597_C02(SCH_1):PAGE10; MAX_WATTAGE: 62.5mW; NV_PN: 195-2655-000; PATH: I178; PHYS_PAGE: 10; ROT: 2; SEC: 1; SIGNAL_MODEL: nv_res; TOL: 0.05 ohm; VER: 1; XY: (-11500,5750)
R542 = R: ASSEMBLY: PEX_MINI; CDS_LIB: discrete; CDS_PART_NAME: R_0402-0OHM,0.05 OHM,62.5MW,195-2655-000; CDS_PHYS_PART_NAME: R_0402-0OHM,0.05 OHM,62.5MW,195-2655-000-0OHM,195-2655-000; CDS_SEC: 1; DEVICE_TYPENAME: R_0402-0OHM005OHM625MW195-2655-000-0OHM195-2655-000; DRAWING: @P2597_C02_LIB.P2597_C02(SCH_1):PAGE10; MAX_WATTAGE: 62.5mW; NV_PN: 195-2655-000; PATH: I177; PHYS_PAGE: 10; ROT: 2; SEC: 1; SIGNAL_MODEL: nv_res; TOL: 0.05 ohm; VER: 1; XY: (-11500,6050)
R543 = R#1: ASSEMBLY: PEX_MINI; CDS_LIB: discrete; CDS_PART_NAME: R_0402-47K,5 %,62.5MW,195-0599-000; CDS_PHYS_PART_NAME: R_0402-47K,5 %,62.5MW,195-0599-000-195-0599-000,47K; CDS_SEC: 1; CHIPS_PART_NAME: R; DEVICE_TYPENAME: R_0402-47K5625MW195-0599-000-195-0599-00047K; DRAWING: @P2597_C02_LIB.P2597_C02(SCH_1):PAGE10; MAX_WATTAGE: 62.5mW; NV_PN: 195-0599-000; PATH: I184; PHYS_PAGE: 10; ROT: 0; SEC: 1; SIGNAL_MODEL: nv_res; TOL: 5 %; VER: 2; XY: (-10400,5000)
R545 = R: ASSEMBLY: PEX_MINI; CDS_LIB: discrete; CDS_PART_NAME: R_0402-0OHM,0.05 OHM,62.5MW,195-2655-000; CDS_PHYS_PART_NAME: R_0402-0OHM,0.05 OHM,62.5MW,195-2655-000-0OHM,195-2655-000; CDS_SEC: 1; DEVICE_TYPENAME: R_0402-0OHM005OHM625MW195-2655-000-0OHM195-2655-000; DRAWING: @P2597_C02_LIB.P2597_C02(SCH_1):PAGE10; MAX_WATTAGE: 62.5mW; NV_PN: 195-2655-000; PATH: I137; PHYS_PAGE: 10; ROT: 2; SEC: 1; SIGNAL_MODEL: nv_res; TOL: 0.05 ohm; VER: 1; XY: (-10750,6050)
R546 = R#1: ASSEMBLY: PEX_MINI; CDS_LIB: discrete; CDS_PART_NAME: R_0402-47K,5 %,62.5MW,195-0599-000; CDS_PHYS_PART_NAME: R_0402-47K,5 %,62.5MW,195-0599-000-195-0599-000,47K; CDS_SEC: 1; CHIPS_PART_NAME: R; DEVICE_TYPENAME: R_0402-47K5625MW195-0599-000-195-0599-00047K; DRAWING: @P2597_C02_LIB.P2597_C02(SCH_1):PAGE10; MAX_WATTAGE: 62.5mW; NV_PN: 195-0599-000; PATH: I186; PHYS_PAGE: 10; ROT: 0; SEC: 1; SIGNAL_MODEL: nv_res; TOL: 5 %; VER: 2; XY: (-11200,5000)
R551 = R: ASSEMBLY: PEX_MINI; CDS_LIB: discrete; CDS_PART_NAME: R_0402-0OHM,0.05 OHM,62.5MW,195-2655-000; CDS_PHYS_PART_NAME: R_0402-0OHM,0.05 OHM,62.5MW,195-2655-000-0OHM,195-2655-000; CDS_SEC: 1; DEVICE_TYPENAME: R_0402-0OHM005OHM625MW195-2655-000-0OHM195-2655-000; DRAWING: @P2597_C02_LIB.P2597_C02(SCH_1):PAGE10; MAX_WATTAGE: 62.5mW; NV_PN: 195-2655-000; PATH: I144; PHYS_PAGE: 10; ROT: 2; SEC: 1; SIGNAL_MODEL: DEFAULT_RESISTOR_0.001OHM_2_1; TOL: 0.05 ohm; VER: 1; XY: (-3600,5650)
R552 = R: ASSEMBLY: PEX_MINI; CDS_LIB: discrete; CDS_PART_NAME: R_0402-0OHM,0.05 OHM,62.5MW,195-2655-000; CDS_PHYS_PART_NAME: R_0402-0OHM,0.05 OHM,62.5MW,195-2655-000-0OHM,195-2655-000; CDS_SEC: 1; DEVICE_TYPENAME: R_0402-0OHM005OHM625MW195-2655-000-0OHM195-2655-000; DRAWING: @P2597_C02_LIB.P2597_C02(SCH_1):PAGE10; MAX_WATTAGE: 62.5mW; NV_PN: 195-2655-000; PATH: I146; PHYS_PAGE: 10; ROT: 2; SEC: 1; SIGNAL_MODEL: DEFAULT_RESISTOR_0.001OHM_2_1; TOL: 0.05 ohm; VER: 1; XY: (-3600,5600)
R553 = R: ASSEMBLY: PEX_MINI; CDS_LIB: discrete; CDS_PART_NAME: R_0402-0OHM,0.05 OHM,62.5MW,195-2655-000; CDS_PHYS_PART_NAME: R_0402-0OHM,0.05 OHM,62.5MW,195-2655-000-0OHM,195-2655-000; CDS_SEC: 1; DEVICE_TYPENAME: R_0402-0OHM005OHM625MW195-2655-000-0OHM195-2655-000; DRAWING: @P2597_C02_LIB.P2597_C02(SCH_1):PAGE10; MAX_WATTAGE: 62.5mW; NV_PN: 195-2655-000; PATH: I145; PHYS_PAGE: 10; ROT: 2; SEC: 1; SIGNAL_MODEL: DEFAULT_RESISTOR_0.001OHM_2_1; TOL: 0.05 ohm; VER: 1; XY: (-3600,5550)
R554 = R: ASSEMBLY: PEX_MINI; CDS_LIB: discrete; CDS_PART_NAME: R_0402-0OHM,0.05 OHM,62.5MW,195-2655-000; CDS_PHYS_PART_NAME: R_0402-0OHM,0.05 OHM,62.5MW,195-2655-000-0OHM,195-2655-000; CDS_SEC: 1; DEVICE_TYPENAME: R_0402-0OHM005OHM625MW195-2655-000-0OHM195-2655-000; DRAWING: @P2597_C02_LIB.P2597_C02(SCH_1):PAGE10; MAX_WATTAGE: 62.5mW; NV_PN: 195-2655-000; PATH: I147; PHYS_PAGE: 10; ROT: 2; SEC: 1; SIGNAL_MODEL: DEFAULT_RESISTOR_0.001OHM_2_1; TOL: 0.05 ohm; VER: 1; XY: (-3600,5500)
R555 = R: ASSEMBLY: PEX_MINI; CDS_LIB: discrete; CDS_PART_NAME: R_0402-0OHM,0.05 OHM,62.5MW,195-2655-000; CDS_PHYS_PART_NAME: R_0402-0OHM,0.05 OHM,62.5MW,195-2655-000-0OHM,195-2655-000; CDS_SEC: 1; DEVICE_TYPENAME: R_0402-0OHM005OHM625MW195-2655-000-0OHM195-2655-000; DRAWING: @P2597_C02_LIB.P2597_C02(SCH_1):PAGE10; MAX_WATTAGE: 62.5mW; NV_PN: 195-2655-000; PATH: I160; PHYS_PAGE: 10; ROT: 2; SEC: 1; SIGNAL_MODEL: DEFAULT_RESISTOR_0.001OHM_2_1; TOL: 0.05 ohm; VER: 1; XY: (-3300,5450)
R556 = R: ASSEMBLY: PEX_MINI; CDS_LIB: discrete; CDS_PART_NAME: R_0402-0OHM,0.05 OHM,62.5MW,195-2655-000; CDS_PHYS_PART_NAME: R_0402-0OHM,0.05 OHM,62.5MW,195-2655-000-0OHM,195-2655-000; CDS_SEC: 1; DEVICE_TYPENAME: R_0402-0OHM005OHM625MW195-2655-000-0OHM195-2655-000; DRAWING: @P2597_C02_LIB.P2597_C02(SCH_1):PAGE10; MAX_WATTAGE: 62.5mW; NV_PN: 195-2655-000; PATH: I161; PHYS_PAGE: 10; ROT: 2; SEC: 1; SIGNAL_MODEL: DEFAULT_RESISTOR_0.001OHM_2_1; TOL: 0.05 ohm; VER: 1; XY: (-3300,5400)
U501 = U_I2C_PCA9306: ASSEMBLY: GEN1_CONV; CDS_LIB: digital; CDS_PART_NAME: U_I2C_PCA9306_QFN8-PCA9306AMUTCG,LEVEL SHIFTER,115-0785-000; CDS_PHYS_PART_NAME: U_I2C_PCA9306_QFN8-PCA9306AMUTCG,LEVEL SHIFTER,115-0785-000-115-0785-000; CDS_SEC: 1; DEVICE_TYPENAME: U_I2C_PCA9306_QFN8-PCA9306AMUTCGLEVELSHIFTER115-0785-000-115-0785-000; DRAWING: @P2597_C02_LIB.P2597_C02(SCH_1):PAGE10; FUNCTION: Level Shifter; NV_NAME: PCA9306AMUTCG; NV_PN: 115-0785-000; PACK_TYPE: QFN8; PATH: I268; PHYS_PAGE: 10; ROT: 2; SEC: 1; SEC_TYPE: QFN8; VER: 2; XY: (-9550,2450)
Y501 = OSC_4PIN: ASSEMBLY: PEX_MINI; CDS_LIB: clocks; CDS_PART_NAME: OSC_4PIN_SMD_32X25-ASHEK-32.768KHZ-L-T,32.768KHZ,25PPM,5PPM,-1PPM,15PF,086-0143-000; CDS_PHYS_PART_NAME: OSC_4PIN_SMD_32X25-ASHEK-32.768KHZ-L-T,32.768KHZ,25PPM,5PPM,-1PPM,15PF,086-0143-000-086-0143-000,32.768KHZ; CDS_SEC: 1; DEVICE_TYPENAME: OSC_4PIN_SMD_32X25-ASHEK-32768KHZ-L-T32768KHZ25PPM5PPM-1PPM15PF086-0143-000-086-0143-00032768KHZ; DRAWING: @P2597_C02_LIB.P2597_C02(SCH_1):PAGE10; LOAD_CAPACITANCE: 15pF; NV_NAME: ASHEK-32.768KHZ-L-T; NV_PN: 086-0143-000; PACK_TYPE: SMD_32X25; PATH: I180; PHYS_PAGE: 10; ROT: 0; SEC: 1; SEC_TYPE: SMD_32X25; TOL: 25ppm; TOL_AGE: 5ppm; TOL_TOTAL: -1ppm; VER: 1; XY: (-9750,6000)
C532 = C: ASSEMBLY: SDCARD; CDS_LIB: discrete; CDS_PART_NAME: C_0402-12PF,C0G,5%,50V,035-0014-000; CDS_PHYS_PART_NAME: C_0402-12PF,C0G,5%,50V,035-0014-000-035-0014-000,12PF; CDS_SEC: 1; DEVICE_TYPENAME: C_0402-12PFC0G550V035-0014-000-035-0014-00012PF; DRAWING: @P2597_C02_LIB.P2597_C02(SCH_1):PAGE11; MAT: C0G; MAX_VOLTAGE: 50V; NV_PN: 035-0014-000; PATH: I14; PHYS_PAGE: 11; ROT: 0; SEC: 1; SIGNAL_MODEL: DEFAULT_CAPACITOR_12pF_2_1; SKU: NO STUFF; TOL: 5%; VER: 1; XY: (-4800,2850)
C533 = C: ASSEMBLY: SDCARD; CDS_LIB: discrete; CDS_PART_NAME: C_0402-0.1UF,X7R,10%,16V,036-0014-000; CDS_PHYS_PART_NAME: C_0402-0.1UF,X7R,10%,16V,036-0014-000-0.1UF,036-0014-000; CDS_SEC: 1; DEVICE_TYPENAME: C_0402-01UFX7R1016V036-0014-000-01UF036-0014-000; DRAWING: @P2597_C02_LIB.P2597_C02(SCH_1):PAGE11; MAT: X7R; MAX_VOLTAGE: 16V; NV_PN: 036-0014-000; PATH: I36; PHYS_PAGE: 11; ROT: 0; SEC: 1; SIGNAL_MODEL: DEFAULT_CAPACITOR_100000pF_2_1; TOL: 10%; VER: 1; XY: (-3500,5050)
C534 = C: ASSEMBLY: SDCARD; CDS_LIB: discrete; CDS_PART_NAME: C_0603-10UF,X5R,20%,6.3V,039-0135-000; CDS_PHYS_PART_NAME: C_0603-10UF,X5R,20%,6.3V,039-0135-000-039-0135-000,10UF; CDS_SEC: 1; DEVICE_TYPENAME: C_0603-10UFX5R2063V039-0135-000-039-0135-00010UF; DRAWING: @P2597_C02_LIB.P2597_C02(SCH_1):PAGE11; MAT: X5R; MAX_VOLTAGE: 6.3V; NV_PN: 039-0135-000; PATH: I34; PHYS_PAGE: 11; ROT: 0; SEC: 1; SIGNAL_MODEL: DEFAULT_CAPACITOR_1e+07pF_2_1; TOL: 20%; VER: 1; XY: (-3850,5050)
C535 = C: ASSEMBLY: DISPLAY; CDS_LIB: discrete; CDS_PART_NAME: C_0402-1UF,X5R,10%,6.3V,039-0008-000; CDS_PHYS_PART_NAME: C_0402-1UF,X5R,10%,6.3V,039-0008-000-039-0008-000,1UF; CDS_SEC: 1; DEVICE_TYPENAME: C_0402-1UFX5R1063V039-0008-000-039-0008-0001UF; DRAWING: @P2597_C02_LIB.P2597_C02(SCH_1):PAGE11; MAT: X5R; MAX_VOLTAGE: 6.3V; NV_PN: 039-0008-000; PATH: I57; PHYS_PAGE: 11; ROT: 0; SEC: 1; SIGNAL_MODEL: DEFAULT_CAPACITOR_1e+06pF_2_1; TOL: 10%; VER: 1; XY: (-6650,5550)
D504 = D_ESD_DIFFPAIR#1: ASSEMBLY: SDCARD; BREAKDOWN_VOLTAGE_MIN_TYP: 6V; CAPACITANCE_MAX_TYP: 0.5pF; CDS_LIB: discrete; CDS_PART_NAME: D_ESD_DIFFPAIR_DUAL-TPD4E05U06,2 DIFFPAIR,UNI-DIRECTIONAL,5.5V,10UA,6V,10V@1A,0.5PF,090-0231-000; CDS_PHYS_PART_NAME: D_ESD_DIFFPAIR_DUAL-TPD4E05U06,2 DIFFPAIR,UNI-DIRECTIONAL,5.5V,10UA,6V,10V@1A,0.5PF,090-0231-000-090-0231-000; CDS_SEC: 2; CHIPS_PART_NAME: D_ESD_DIFFPAIR; CLAMPING_VOLTAGE: 10V@1A; CONFIGURATION: 2 Diffpair; CaptureCellPackProp: D_ESD_DIFFPAIR#1B; DEVICE_TYPENAME: D_ESD_DIFFPAIR_DUAL-TPD4E05U062DIFFPAIRUNI-DIRECTIONAL55V10UA6V10V1A05PF090-0231-000-090-0231-000; DRAWING: @P2597_C02_LIB.P2597_C02(SCH_1):PAGE11; MAX_REVERSE_LEAKAGE_CURRENT: 10uA; MAX_REVERSE_VOLTAGE: 5.5V; NV_NAME: TPD4E05U06; NV_PN: 090-0231-000; PACK_TYPE: DUAL; PATH: I11; PHYS_PAGE: 11; POLARITY: Uni-Directional; ROT: 2; SEC: 2; SEC_TYPE: DUAL; VER: 2; XY: (-6700,2750)
D505 = D_ESD_DIFFPAIR#1: ASSEMBLY: SDCARD; BREAKDOWN_VOLTAGE_MIN_TYP: 6V; CAPACITANCE_MAX_TYP: 0.5pF; CDS_LIB: discrete; CDS_PART_NAME: D_ESD_DIFFPAIR_DUAL-TPD4E05U06,2 DIFFPAIR,UNI-DIRECTIONAL,5.5V,10UA,6V,10V@1A,0.5PF,090-0231-000; CDS_PHYS_PART_NAME: D_ESD_DIFFPAIR_DUAL-TPD4E05U06,2 DIFFPAIR,UNI-DIRECTIONAL,5.5V,10UA,6V,10V@1A,0.5PF,090-0231-000-090-0231-000; CDS_SEC: 2; CHIPS_PART_NAME: D_ESD_DIFFPAIR; CLAMPING_VOLTAGE: 10V@1A; CONFIGURATION: 2 Diffpair; CaptureCellPackProp: D_ESD_DIFFPAIR#1B; DEVICE_TYPENAME: D_ESD_DIFFPAIR_DUAL-TPD4E05U062DIFFPAIRUNI-DIRECTIONAL55V10UA6V10V1A05PF090-0231-000-090-0231-000; DRAWING: @P2597_C02_LIB.P2597_C02(SCH_1):PAGE11; MAX_REVERSE_LEAKAGE_CURRENT: 10uA; MAX_REVERSE_VOLTAGE: 5.5V; NV_NAME: TPD4E05U06; NV_PN: 090-0231-000; PACK_TYPE: DUAL; PATH: I32; PHYS_PAGE: 11; POLARITY: Uni-Directional; ROT: 0; SEC: 2; VER: 2; XY: (-4600,4850)
J12 = CON_SD_SOCKET: ANGLE: 90; ASSEMBLY: SDCARD; CDS_LIB: electro_mechanic; CDS_PART_NAME: CON_SD_SOCKET_PUSH_IN_OUT-SD_SOCKET,N/A,N/A,90,YES,N/A,N/A,YES,YES,250VAC,0.5A,220-0030-000; CDS_PHYS_PART_NAME: CON_SD_SOCKET_PUSH_IN_OUT-SD_SOCKET,N/A,N/A,90,YES,N/A,N/A,YES,YES,250VAC,0.5A,220-0030-000-220-0030-000; CDS_SEC: 1; DEVICE_TYPENAME: CON_SD_SOCKET_PUSH_IN_OUT-SD_SOCKETNANA90YESNANAYESYES250VAC05A220-0030-000-220-0030-000; DRAWING: @P2597_C02_LIB.P2597_C02(SCH_1):PAGE11; EMI_GROUND_TAB: YES; GENDER: N/A; LATCHING: N/A; MAX_CURRENT: 0.5A; MAX_VOLTAGE: 250VAC; NV_NAME: SD_SOCKET; NV_PN: 220-0030-000; PACK_TYPE: PUSH_IN_OUT; PATH: I38; PHYS_PAGE: 11; PITCH: N/A; REFLOW: YES; ROT: 0; SEC: 1; SEC_TYPE: PUSH_IN_OUT; SHIELDED: YES; SHROUDED: N/A; VER: 1; XY: (-2600,3850)
Q509 = Q_FET_N_ENH#2: ASSEMBLY: SDCARD; CDS_LIB: discrete; CDS_PART_NAME: Q_FET_N_ENH_SOT323_1G1D1S-NTS4001NT1G,30V,1500MOHM@10V / 1500MOHM@4.5V / 1500MOHM@2.5V,0.27A,0.8A,20V,0.33W,[ ]@10V / [ ]@4.5VA; CDS_PHYS_PART_NAME: Q_FET_N_ENH_SOT323_1G1D1S-NTS4001NT1G,30V,1500MOHM@10V / 1500MOHM@4.5V / 1500MOHM@2.5V,0.27A,0.8A,20V,0.33W,[ ]@10V / [ ]@4.5VB; CDS_SEC: 1; CONTINUOUS_CURRENT: 0.27A; CaptureCellPackProp: Q_FET_N_ENH__sym_2##2; DEVICE_TYPENAME: Q_FET_N_ENH_SOT323_1G1D1S-NTS4001NT1G30V1500MOHM10V1500MOHM45V1500MOHM25V027A08A20V033W10V45VB; DRAWING: @P2597_C02_LIB.P2597_C02(SCH_1):PAGE11; MAX_CURRENT: 0.8A; MAX_VOLTAGE: 30V; MAX_WATTAGE: 0.33W; NV_NAME: NTS4001NT1G; NV_PN: 300-0485-000; PACK_TYPE: SOT323_1G1D1S; PATH: I53; PHYS_PAGE: 11; Q_G: [ ]@10V / [ ]@4.5V / [ ]@2.5V; ROT: 0; R_DS_ON: 1500mohm@10V / 1500mohm@4.5V / 1500mohm@2.5V; SEC: 1; SEC_TYPE: SOT323_1G1D1S; VER: 2; V_BE_GS: 20V; XY: (-7500,5250)
R589 = R: ASSEMBLY: SDCARD; CDS_LIB: discrete; CDS_PART_NAME: R_0402-10OHM,1 %,62.5MW,195-0001-000; CDS_PHYS_PART_NAME: R_0402-10OHM,1 %,62.5MW,195-0001-000-10OHM,195-0001-000; CDS_SEC: 1; DEVICE_TYPENAME: R_0402-10OHM1625MW195-0001-000-10OHM195-0001-000; DRAWING: @P2597_C02_LIB.P2597_C02(SCH_1):PAGE11; MAX_WATTAGE: 62.5mW; NV_PN: 195-0001-000; PATH: I60; PHYS_PAGE: 11; ROT: 0; SEC: 1; SIGNAL_MODEL: nv_res; TOL: 1%; VER: 1; XY: (-8450,4600)
R590 = R: ASSEMBLY: SDCARD; CDS_LIB: discrete; CDS_PART_NAME: R_0402-10OHM,1 %,62.5MW,195-0001-000; CDS_PHYS_PART_NAME: R_0402-10OHM,1 %,62.5MW,195-0001-000-10OHM,195-0001-000; CDS_SEC: 1; DEVICE_TYPENAME: R_0402-10OHM1625MW195-0001-000-10OHM195-0001-000; DRAWING: @P2597_C02_LIB.P2597_C02(SCH_1):PAGE11; MAX_WATTAGE: 62.5mW; NV_PN: 195-0001-000; PATH: I58; PHYS_PAGE: 11; ROT: 0; SEC: 1; SIGNAL_MODEL: nv_res; TOL: 1%; VER: 1; XY: (-8450,4650)
R591 = R: ASSEMBLY: SDCARD; CDS_LIB: discrete; CDS_PART_NAME: R_0402-47K,5 %,62.5MW,195-0599-000; CDS_PHYS_PART_NAME: R_0402-47K,5 %,62.5MW,195-0599-000-195-0599-000,47K; CDS_SEC: 1; DEVICE_TYPENAME: R_0402-47K5625MW195-0599-000-195-0599-00047K; DRAWING: @P2597_C02_LIB.P2597_C02(SCH_1):PAGE11; MAX_WATTAGE: 62.5mW; NV_PN: 195-0599-000; PATH: I55; PHYS_PAGE: 11; ROT: 0; SEC: 1; SIGNAL_MODEL: nv_res; TOL: 5%; VER: 1; XY: (-7100,5700)
R593 = R: ASSEMBLY: SDCARD; CDS_LIB: discrete; CDS_PART_NAME: R_0402-0OHM,0.05 OHM,62.5MW,195-2655-000; CDS_PHYS_PART_NAME: R_0402-0OHM,0.05 OHM,62.5MW,195-2655-000-0OHM,195-2655-000; CDS_SEC: 1; DEVICE_TYPENAME: R_0402-0OHM005OHM625MW195-2655-000-0OHM195-2655-000; DRAWING: @P2597_C02_LIB.P2597_C02(SCH_1):PAGE11; MAX_WATTAGE: 62.5mW; NV_PN: 195-2655-000; PATH: I59; PHYS_PAGE: 11; ROT: 0; SEC: 1; SIGNAL_MODEL: nv_res; TOL: 0.05 ohm; VER: 1; XY: (-8450,4250)
R594 = R: ASSEMBLY: SDCARD; CDS_LIB: discrete; CDS_PART_NAME: R_0402-10OHM,1 %,62.5MW,195-0001-000; CDS_PHYS_PART_NAME: R_0402-10OHM,1 %,62.5MW,195-0001-000-10OHM,195-0001-000; CDS_SEC: 1; DEVICE_TYPENAME: R_0402-10OHM1625MW195-0001-000-10OHM195-0001-000; DRAWING: @P2597_C02_LIB.P2597_C02(SCH_1):PAGE11; MAX_WATTAGE: 62.5mW; NV_PN: 195-0001-000; PATH: I63; PHYS_PAGE: 11; ROT: 0; SEC: 1; SIGNAL_MODEL: nv_res; TOL: 1%; VER: 1; XY: (-8450,4350)
R595 = R: ASSEMBLY: SDCARD; CDS_LIB: discrete; CDS_PART_NAME: R_0402-10OHM,1 %,62.5MW,195-0001-000; CDS_PHYS_PART_NAME: R_0402-10OHM,1 %,62.5MW,195-0001-000-10OHM,195-0001-000; CDS_SEC: 1; DEVICE_TYPENAME: R_0402-10OHM1625MW195-0001-000-10OHM195-0001-000; DRAWING: @P2597_C02_LIB.P2597_C02(SCH_1):PAGE11; MAX_WATTAGE: 62.5mW; NV_PN: 195-0001-000; PATH: I62; PHYS_PAGE: 11; ROT: 0; SEC: 1; SIGNAL_MODEL: nv_res; TOL: 1%; VER: 1; XY: (-8450,4500)
R596 = R: ASSEMBLY: SDCARD; CDS_LIB: discrete; CDS_PART_NAME: R_0402-10OHM,1 %,62.5MW,195-0001-000; CDS_PHYS_PART_NAME: R_0402-10OHM,1 %,62.5MW,195-0001-000-10OHM,195-0001-000; CDS_SEC: 1; DEVICE_TYPENAME: R_0402-10OHM1625MW195-0001-000-10OHM195-0001-000; DRAWING: @P2597_C02_LIB.P2597_C02(SCH_1):PAGE11; MAX_WATTAGE: 62.5mW; NV_PN: 195-0001-000; PATH: I61; PHYS_PAGE: 11; ROT: 0; SEC: 1; SIGNAL_MODEL: nv_res; TOL: 1%; VER: 1; XY: (-8450,4550)
U503 = U_POWER_SW#1: ASSEMBLY: SDCARD; CDS_LIB: power_supply; CDS_PART_NAME: U_POWER_SW_SOT23_5C-APL3511DBI-TRG,-9999V..9999V,-9999V..9999V,9999A,SWITCH,115-1238-000; CDS_PHYS_PART_NAME: U_POWER_SW_SOT23_5C-APL3511DBI-TRG,-9999V..9999V,-9999V..9999V,9999A,SWITCH,115-1238-000-115-1238-000; CDS_SEC: 1; DEVICE_TYPENAME: U_POWER_SW_SOT23_5C-APL3511DBI-TRG-9999V9999V-9999V9999V9999ASWITCH115-1238-000-115-1238-000; DRAWING: @P2597_C02_LIB.P2597_C02(SCH_1):PAGE11; MAX_CURRENT: 9999A; MAX_VOLTAGE: -9999V..9999V; NV_NAME: APL3511DBI-TRG; NV_PN: 115-1238-000; OUTPUT_VOLTAGE: -9999V..9999V; PACK_TYPE: SOT23_5C; PATH: I52; PHYS_PAGE: 11; ROT: 0; SEC: 1; SEC_TYPE: SOT23_5C; TYPE: Switch; VER: 11; XY: (-5800,5550)

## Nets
GND: C506.2 C507.2 C509.2 C510.2 C511.2 C512.2 C514.2 C515.2 C532.2 C533.2 C534.2 C535.2 D504.3(GND1) D505.3(GND1) J12.3(VSS_1) J12.6(VSS_2) J12.11(COMMON) J12.13(GND_EMI1) J12.14(GND_EMI2) J12.15(GND_EMI3) J18.1(GND_11) J18.7(GND_10) J18.18(GND_9) J18.33(GND_8) J18.39(GND_7) J18.45(GND_6) J18.51(GND_5) J18.57(GND_4) J18.63(GND_3) J18.69(GND_2) J18.75(GND_1) J18.76(GND_13) J18.77(GND_12) MEC10.1A MEC10.1B Q509.2(S) R540.2 U501.1(GND) U503.2(GND) Y501.2(GND) ; also on sheet 1 2 3 4 5 6 7 9 10 11 12 13 14 15 16 17 18 19 20 21 22 25 26 30
VDD_1V8: C506.1 Q39.1(G) Q504.1(G) R320.1 R541.2 R546.1 U501.2(VREF1) ; also on sheet 4 5 9 10 12 13 16 17 18 19 20 22 30
VDD_3V3_SYS: C535.1 R144.1 R193.1 R516.1 R524.1 R525.1 R534.1 R538.1 R542.2 R543.1 R591.2 U503.5(IN) ; also on sheet 1 2 3 4 5 6 12 13 17 18 19 25
VDD_3V3_SYS_M2: C509.1 C510.1 C511.1 C512.1 CR3.2(A) CR4.2(A) J18.2(3P3V_4) J18.4(3P3V_3) J18.72(3P3V_2) J18.74(3P3V_1) R193.4
VDD_M2_IN_N: R193.3 ; also on sheet 2
VDD_M2_IN_P: R193.2 ; also on sheet 2
VDD_OSC: C514.1 R541.1 R542.1 R545.2 Y501.4(VCC)
AP_WAKE_MDM_1V8: R530.2 ; also on sheet 28
AP_WAKE_MDM_1V8_R: J18.40(VENDOR_DEFINED_2) R530.1
BT2_EN: Q504.2(S) R546.2 ; also on sheet 28
BT2_WAKE_AP_L: R532.2 ; also on sheet 28
CHG_OC_L: R145.2 ; also on sheet 18 30
EN_GP0_LVL: C507.1 R534.2 U501.7(VREF2) U501.8(EN)
I2C_GP0_CLK_1V8: R318.2 U501.3(SCL1) ; also on sheet 12 16 17 30
I2C_GP0_DAT_1V8: R319.2 U501.4(SDA1) ; also on sheet 12 16 17 30
I2C_GP0_SCL_3V3_LVL: R316.2 R538.2 U501.6(SCL2) ; also on sheet 18 25
I2C_GP0_SCL_M2: J18.60(I2C_CLK) R316.1 R318.1
I2C_GP0_SDA_3V3_LVL: R317.2 R524.2 U501.5(SDA2) ; also on sheet 18 25
I2C_GP0_SDA_M2: J18.58(I2C_DATA) R317.1 R319.1
I2S2_CLK: J18.8(PCM_CLK_12S_SCK) ; also on sheet 28
I2S2_LRCLK: J18.10(PCM_SYNC_125_WS) ; also on sheet 28
I2S2_SDIN: J18.12(PCM_IN_12S_SD_IN) ; also on sheet 28
I2S2_SDOUT: J18.14(PCM_OUT_12S_SD_OUT) ; also on sheet 28
LED1_L: J18.6(LED1*) R154.1
LED1_R_L: CR4.1(C) R154.2
LED2_L: J18.16(LED2*) R146.1
LED2_R_L: CR3.1(C) R146.2
M2_B_73: J18.73(RESERVED_REFCLKN1) R145.1
M2_E_20: J18.20(UART_WAKE*) R532.1
M2_E_59: J18.59(RESERVED_PETP1) R143.1
M2_E_61: J18.61(RESERVED_PETN1) R142.1
M2_E_ALERT_L: J18.62(ALERT*) R537.2
M2_E_ALERT_R_L: Q39.3(D) R516.2 ; also on sheet 13
M2_E_ALERT_RS_L: Q39.2(S) R320.2 R537.1
MDM2AP_READY_1V8: R531.2 ; also on sheet 16 28
MDM2AP_READY_1V8_R: J18.38(VENDOR_DEFINED_3) R531.1
MDM_COLDBOOT_1V8: R528.2 ; also on sheet 28
MDM_COLDBOOT_1V8_R: J18.44(COEX3) R528.1
MDM_EN: R526.2 ; also on sheet 13
MDM_EN_R: J18.48(COEX1) R526.1
MDM_RST_L: R527.2 ; also on sheet 13
MDM_RST_R_L: J18.46(COEX2) R527.1
MDM_WAKE_AP_1V8: R529.2 ; also on sheet 18 28
MDM_WAKE_AP_1V8_R: J18.42(VENDOR_DEFINED_1) R529.1
OSC_EN: C515.1 R545.1 Y501.1(EN)
PCIE_L1_CLKREQ: J18.53(CLKREQO*) R144.2 ; also on sheet 28
PCIE_L1_RST: J18.52(PERST0*) R525.2 ; also on sheet 28
PCIE_WAKE_L: J18.55(PEWAKEO*) ; also on sheet 25 28
PEX_CLK1_N: J18.49(REFCLKNO) ; also on sheet 28
PEX_CLK1_P: J18.47(REFCLKPO) ; also on sheet 28
PEX_RX0_AP_N: J18.43(PERNO) ; also on sheet 28
PEX_RX0_AP_P: J18.41(PERPO) ; also on sheet 28
PEX_TX0_AP_N: C79.2 ; also on sheet 28
PEX_TX0_AP_P: C80.2 ; also on sheet 28
PEX_TX0_C_N: C79.1 J18.37(PETNO)
PEX_TX0_C_P: C80.1 J18.35(PETPO)
SAR_CTRL: R142.2 ; also on sheet 18
SAR_TOUT: R143.2 ; also on sheet 18 30
SD_CARD_SW_PWR: C533.1 C534.1 J12.4(VDD) U503.1(OUT)
SDCARD_CD_L: D504.4(3A) D504.7(3B) J12.10(C_DETECT) ; also on sheet 30
SDCARD_CLK_POL: R593.1 ; also on sheet 30
SDCARD_CLK_R: C532.1 D505.5(4A) D505.6(4B) J12.5(CLK) R593.2
SDCARD_CMD_POL: R594.1 ; also on sheet 30
SDCARD_CMD_R: D505.4(3A) D505.7(3B) J12.2(CMD) R594.2
SDCARD_DAT0_POL: R590.1 ; also on sheet 30
SDCARD_DAT0_R: D504.1(1A) D504.10(1B) J12.7(DATA0) R590.2
SDCARD_DAT1_POL: R589.1 ; also on sheet 30
SDCARD_DAT1_R: D504.2(2A) D504.9(2B) J12.8(DATA1) R589.2
SDCARD_DAT2_POL: R596.1 ; also on sheet 30
SDCARD_DAT2_R: D505.1(1A) D505.10(1B) J12.9(DATA2) R596.2
SDCARD_DAT3_POL: R595.1 ; also on sheet 30
SDCARD_DAT3_R: D505.2(2A) D505.9(2B) J12.1(CD_DATA3) R595.2
SDCARD_VDD_EN: Q509.1(G) ; also on sheet 30
SDCARD_VDD_EN_L: Q509.3(D) R591.1 U503.4(EN*)
SDCARD_WP: D504.5(4A) D504.6(4B) J12.12(C_WR_PROTECT) ; also on sheet 30
SDIO_CLK: R556.1 ; also on sheet 28
SDIO_CLK_R: J18.9(SDIO_CLK) R556.2
SDIO_CMD: R555.1 ; also on sheet 28
SDIO_CMD_R: J18.11(SDIO_CMD) R555.2
SDIO_D0: R554.1 ; also on sheet 28
SDIO_D1: R553.1 ; also on sheet 28
SDIO_D2: R552.1 ; also on sheet 28
SDIO_D3: R551.1 ; also on sheet 28
SDIO_DAT0_R: J18.13(SDIO_DATAO) R554.2
SDIO_DAT1_R: J18.15(SDIO_DATA1) R553.2
SDIO_DAT2_R: J18.17(SDIO_DATA2) R552.2
SDIO_DAT3_R: J18.19(SDIO_DATA3) R551.2
SNN_M2_B_65: J18.65(RESERVED_PERP1)
SNN_M2_B_67: J18.67(RESERVED_PERN1)
SNN_M2_B_71: J18.71(RESERVED_REFCLKP1)
SNN_M2_E_64: J18.64(RESERVED)
SNN_M2_E_66: J18.66(UIM_SWP_PERST1*)
SNN_M2_E_68: J18.68(UIM_POWER_SNK_CLKREQ1*)
SNN_M2_E_70: J18.70(UIM_POWER_SRC_GPIO1_PEWAKE1*)
SNN_SDCARD_SW_OC_L: U503.3(OC*)
SUSCLK_32KHZ: J18.50(SUSCLK_32KHZ) Y501.3(OUT)
UART2_CTS: J18.34(UART_CTS) ; also on sheet 28
UART2_RTS: J18.36(UART_RTS) ; also on sheet 28
UART2_RXD: J18.22(UART_RXD) ; also on sheet 28
UART2_TXD: J18.32(UART_TXD) ; also on sheet 28
USB2_D_N: J18.5(USB_DM) ; also on sheet 28
USB2_D_P: J18.3(USB_DP) ; also on sheet 28
W_DISABLE1_L: R539.2 ; also on sheet 13
W_DISABLE1_R_L: J18.56(W_DISABLE1*) R539.1
W_DISABLE2_L: J18.54(W_DISABLE2*) Q504.3(D) R540.1 R543.2
WIFI2_EN: J18.23(SDIO_RESET*) ; also on sheet 28
WIFI2_WAKE_AP_L: J18.21(SDIO_WAKE*) ; also on sheet 28

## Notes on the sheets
sheet 23
- A
- B
- C
- D
- E
- F
- G
- H
- 1
- SD CARD SOCKET
- 1
- 2
- 2
- May need to be tuned for custom CVB (SI and EMI)
- 3
- 3
- 4
- 4
- 5
- 5
- NVIDIA CORPORATION
- 2701 SAN TOMAS EXPRESSWAY
- ASSEMBLY
- <ASSEMBLY_DESCRIPTION>
- SANTA CLARA, CA 95050, USA
- PAGE DETAIL
- SDcard Slot
- NV_PN
- 600-82597-BASE-900
- ALL NVIDIA DESIGN SPECIFICATIONS, REFERENCE SPECIFICATIONS, REFERENCE BOARDS, FILES, DRAWINGS, DIAGNOSTICS, LISTS AND OTHER DOCUMENTS OR INFORMATION (TOGETHER AND SEPARATELY, 'MATERIALS') ARE BEING PROVIDED 'AS IS'. THE MATERIALS MAY
- CONTAIN KNOWN AND UNKNOWN VIOLATIONS OR DEVIATIONS OF INDUSTRY STANDARDS AND SPECIFICATIONS. NVIDIA MAKES NO WARRANTIES, EXPRESSED, IMPLIED, STATUTORY OR OTHERWISE WITH RESPECT TO THE MATERIALS OR OTHERWISE, AND EXPRESSLY DISCLAIMS ALL
- PCB REV
- P2597-C02
- PAGE
- 11 OF 34
- IMPLIED WARRANTIES INCLUDING, WITHOUT LIMITATION, THE WARRANTIES OF DESIGN, OF NONINFRINGEMENT, MERCHANTABILITY OR FITNESS FOR A PARTICULAR PURPOSE, OR ARISING FROM A COURSE OF DEALING, TRADE USAGE, TRADE PRACTICE, OR INDUSTRY STANDARDS.
- BOM REV
- A
- DATE
- 23-OCT-2017
- A
- B
- C
- D
- E
- F
- G
- H
sheet 24
- A
- B
- C
- D
- E
- F
- G
- H
- M.2 KEY E
- 1
- 1
- +/-5%  2Amps
- 2
- 2
- 3
- 3
- 4
- 4
- MDM_POWER_REPORT
- option
- 5
- 5
- Sub 012-0163-000
- NVIDIA CORPORATION
- 2701 SAN TOMAS EXPRESSWAY
- ASSEMBLY
- <ASSEMBLY_DESCRIPTION>
- SANTA CLARA, CA 95050, USA
- PAGE DETAIL
- M.2 KEY E
- NV_PN
- 600-82597-BASE-900
- ALL NVIDIA DESIGN SPECIFICATIONS, REFERENCE SPECIFICATIONS, REFERENCE BOARDS, FILES, DRAWINGS, DIAGNOSTICS, LISTS AND OTHER DOCUMENTS OR INFORMATION (TOGETHER AND SEPARATELY, 'MATERIALS') ARE BEING PROVIDED 'AS IS'. THE MATERIALS MAY
- CONTAIN KNOWN AND UNKNOWN VIOLATIONS OR DEVIATIONS OF INDUSTRY STANDARDS AND SPECIFICATIONS. NVIDIA MAKES NO WARRANTIES, EXPRESSED, IMPLIED, STATUTORY OR OTHERWISE WITH RESPECT TO THE MATERIALS OR OTHERWISE, AND EXPRESSLY DISCLAIMS ALL
- PCB REV
- P2597-C02
- PAGE
- 10 OF 34
- IMPLIED WARRANTIES INCLUDING, WITHOUT LIMITATION, THE WARRANTIES OF DESIGN, OF NONINFRINGEMENT, MERCHANTABILITY OR FITNESS FOR A PARTICULAR PURPOSE, OR ARISING FROM A COURSE OF DEALING, TRADE USAGE, TRADE PRACTICE, OR INDUSTRY STANDARDS.
- BOM REV
- A
- DATE
- 23-OCT-2017
- A
- B
- C
- D
- E
- F
- G
- H
